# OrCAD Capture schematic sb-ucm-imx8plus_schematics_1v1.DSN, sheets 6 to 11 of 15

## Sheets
6 02. Carrier-board interface: size A3; title: SB-UCM-iMX8PLUS  02. Carrier
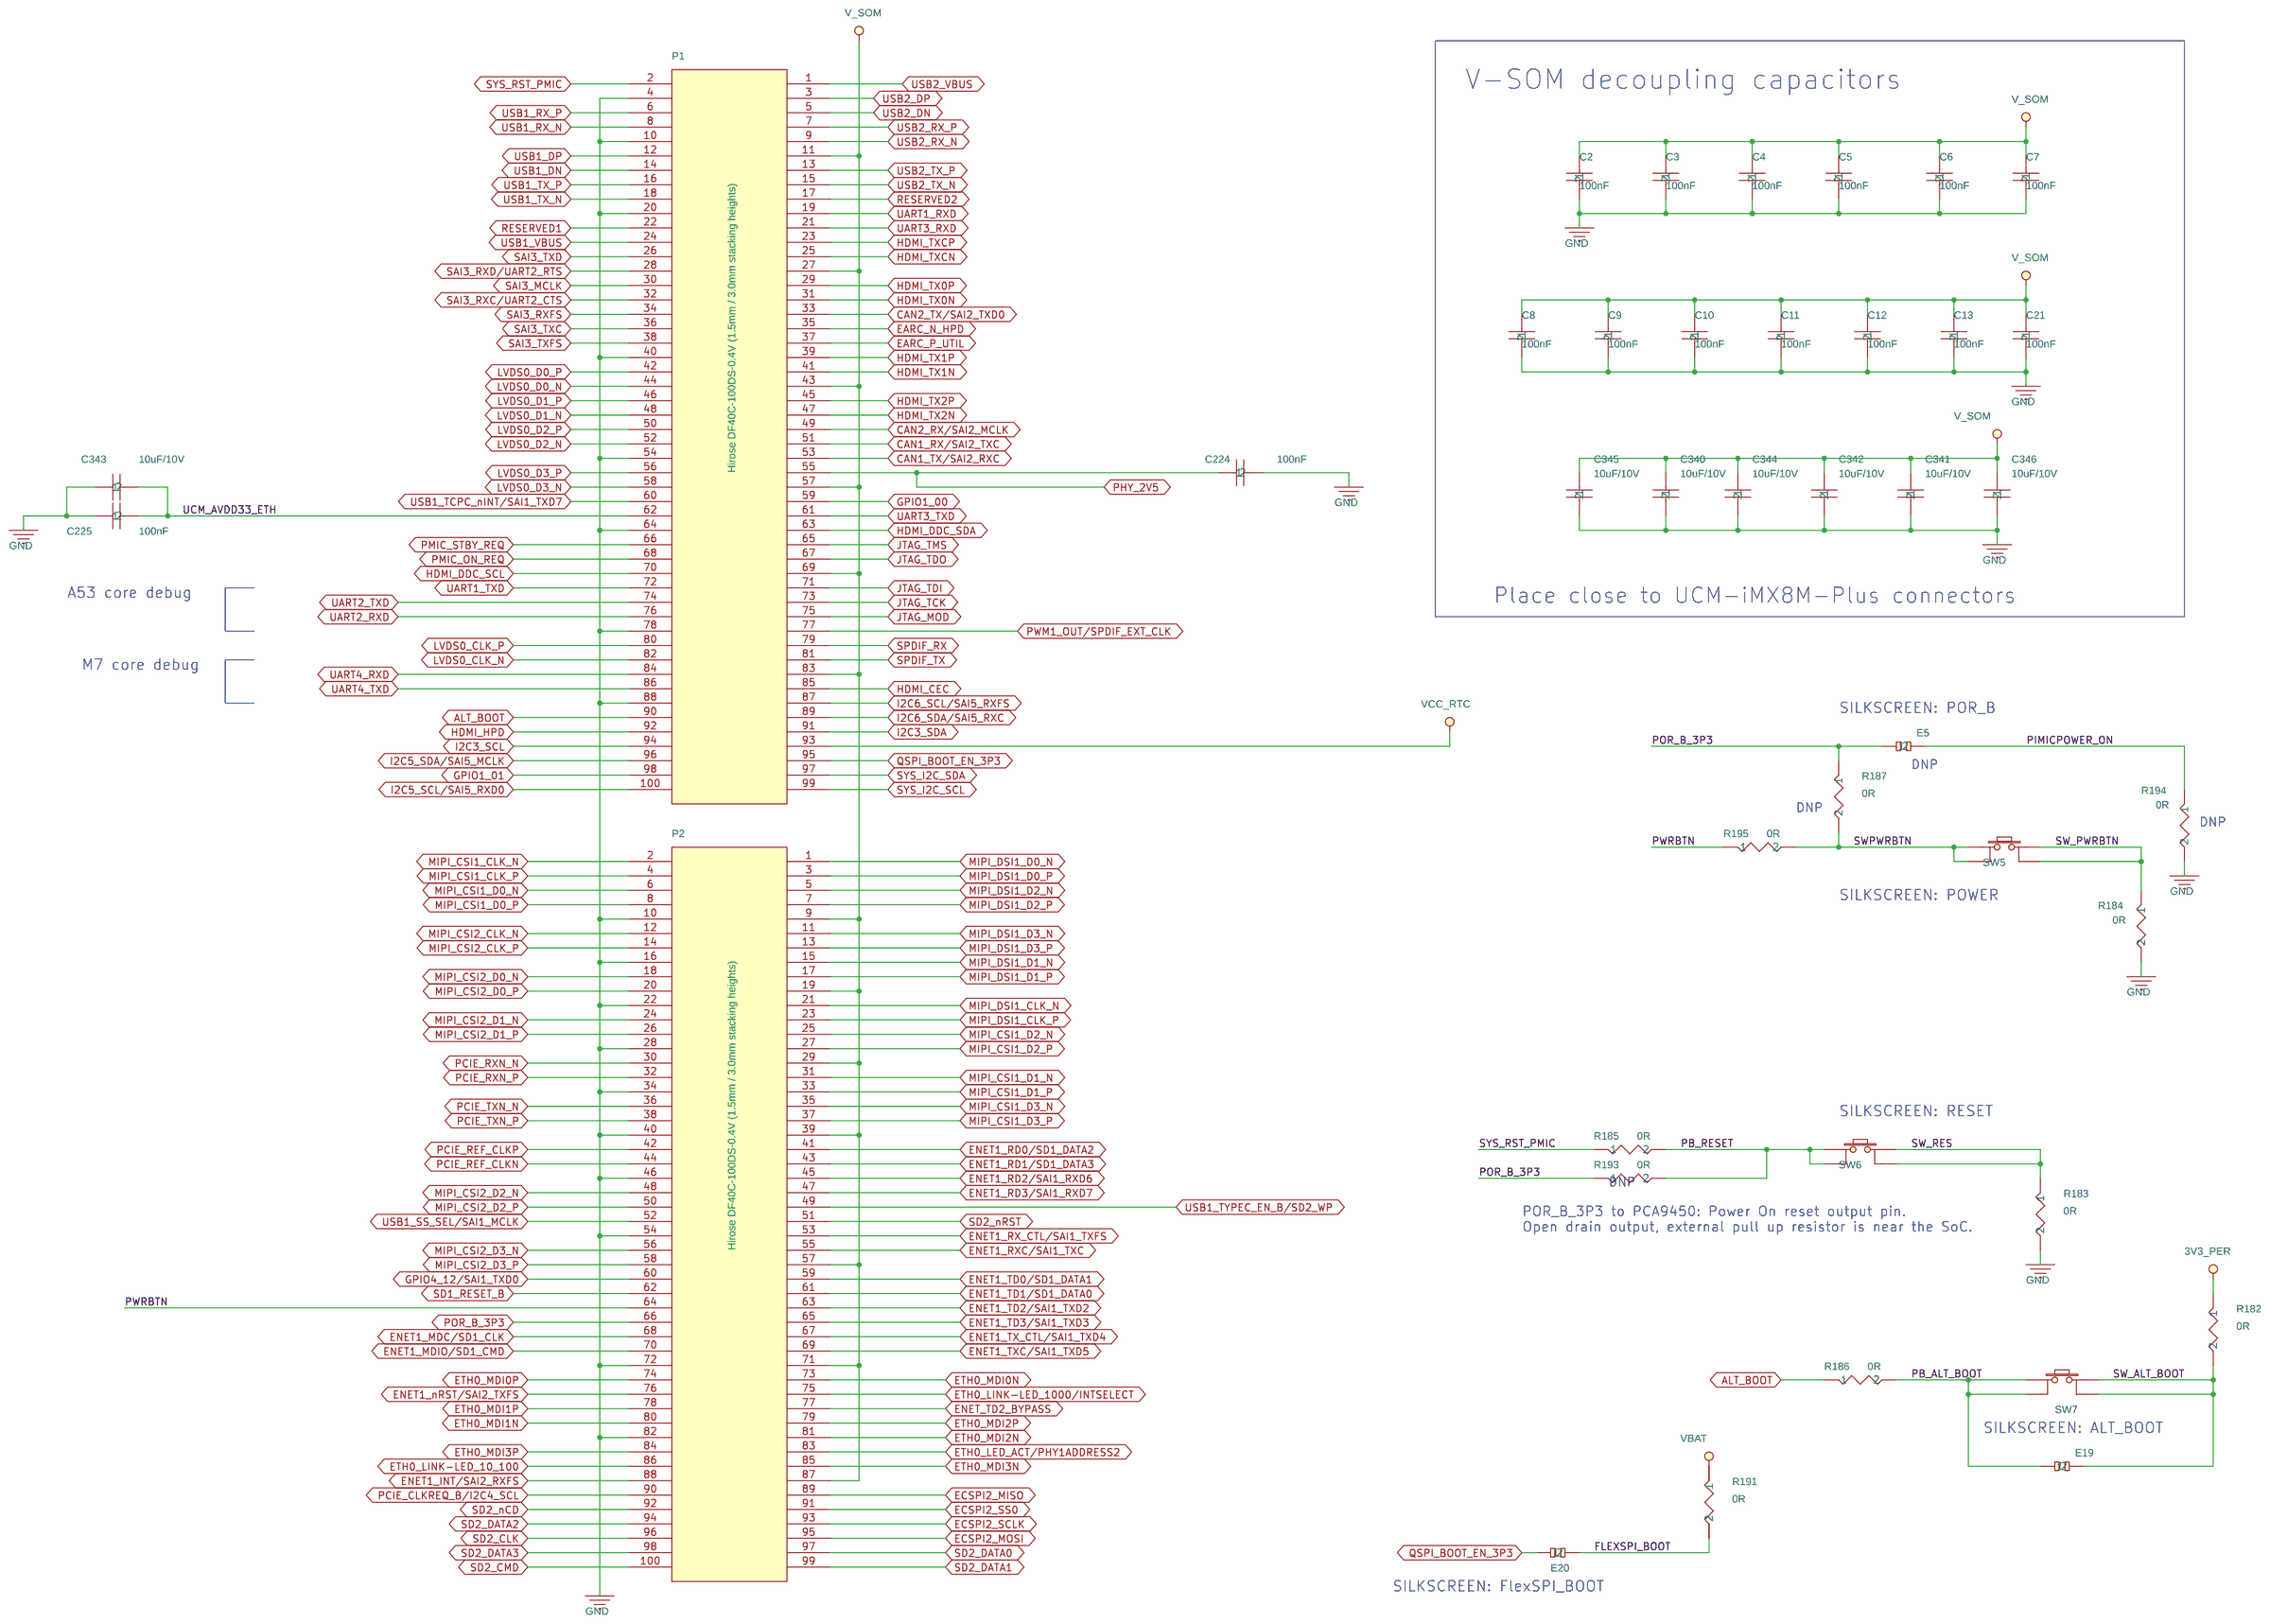
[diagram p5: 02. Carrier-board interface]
7 03. RJ-45 Ethernet connector: size A3; title: SB-UCM-iMX8PLUS      03. Gigabit Ethernet
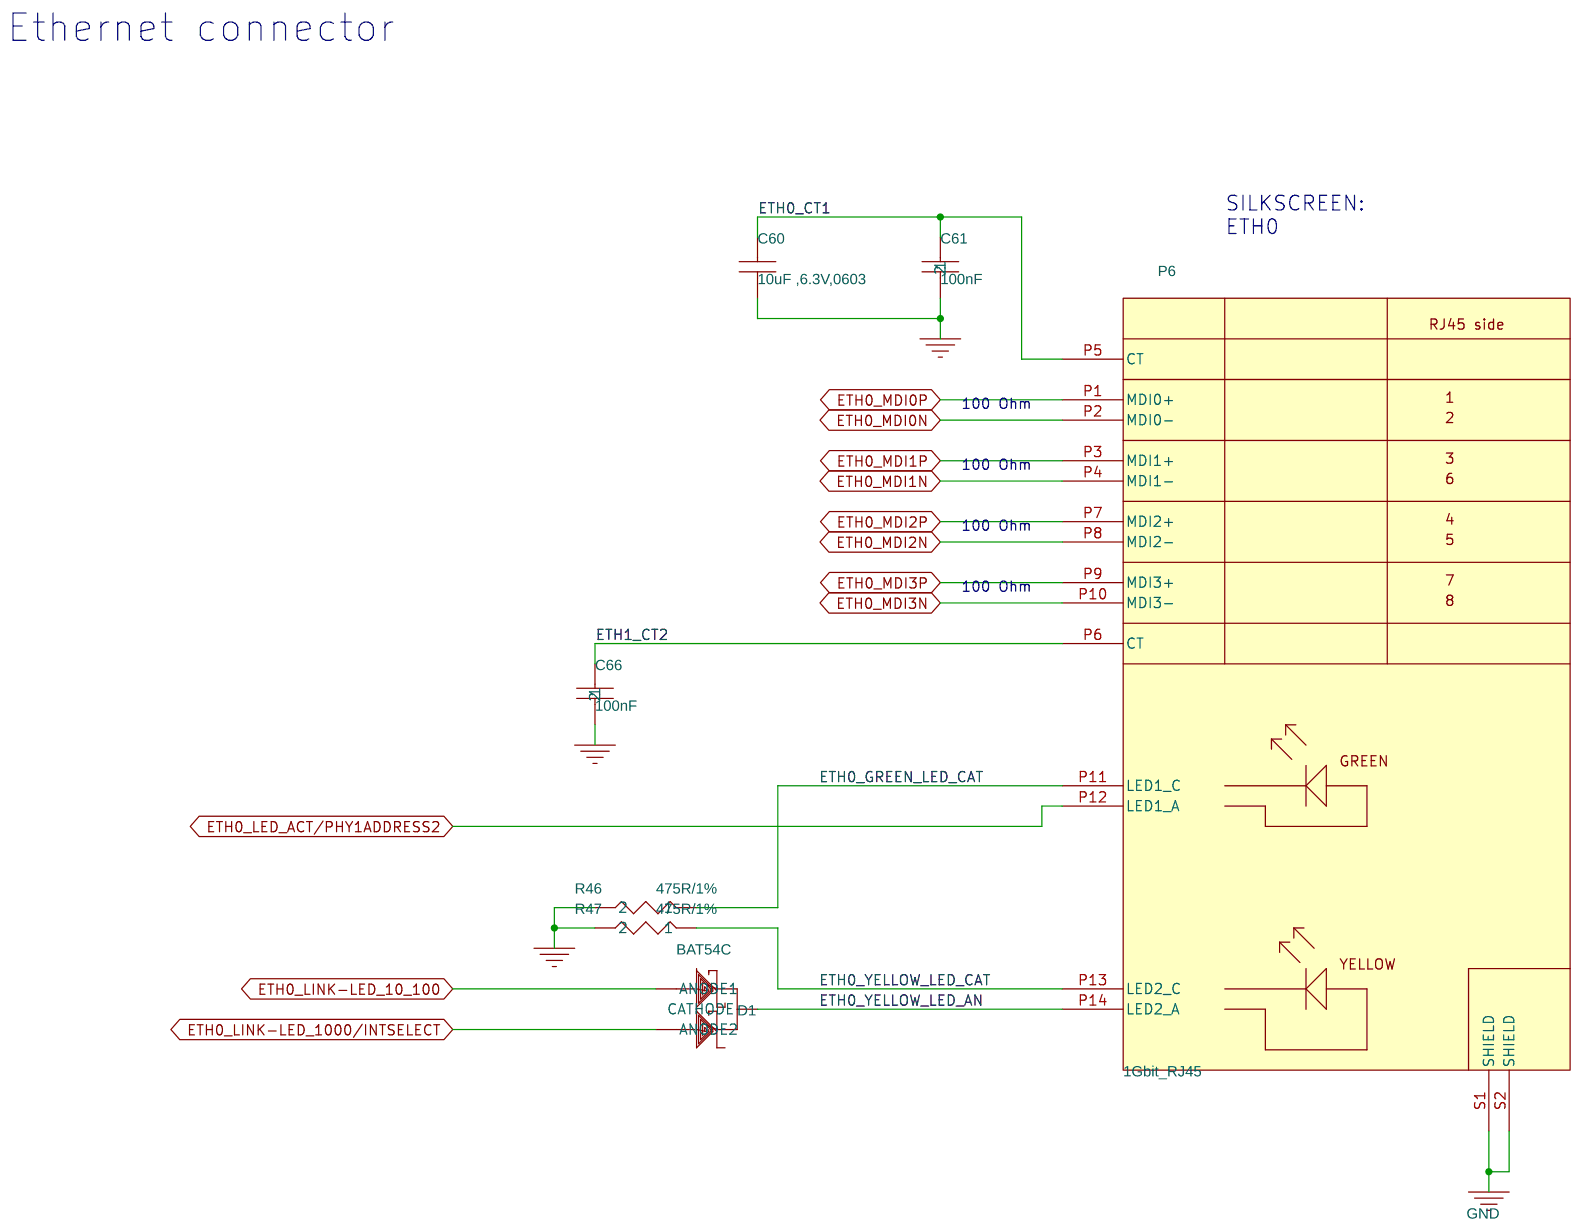
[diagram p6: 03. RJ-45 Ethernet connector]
8 04. USB3.0, Type-C, Host: size A3; title: SB-UCM-iMX8PLUS    04. USB3.0, Type-C, Host
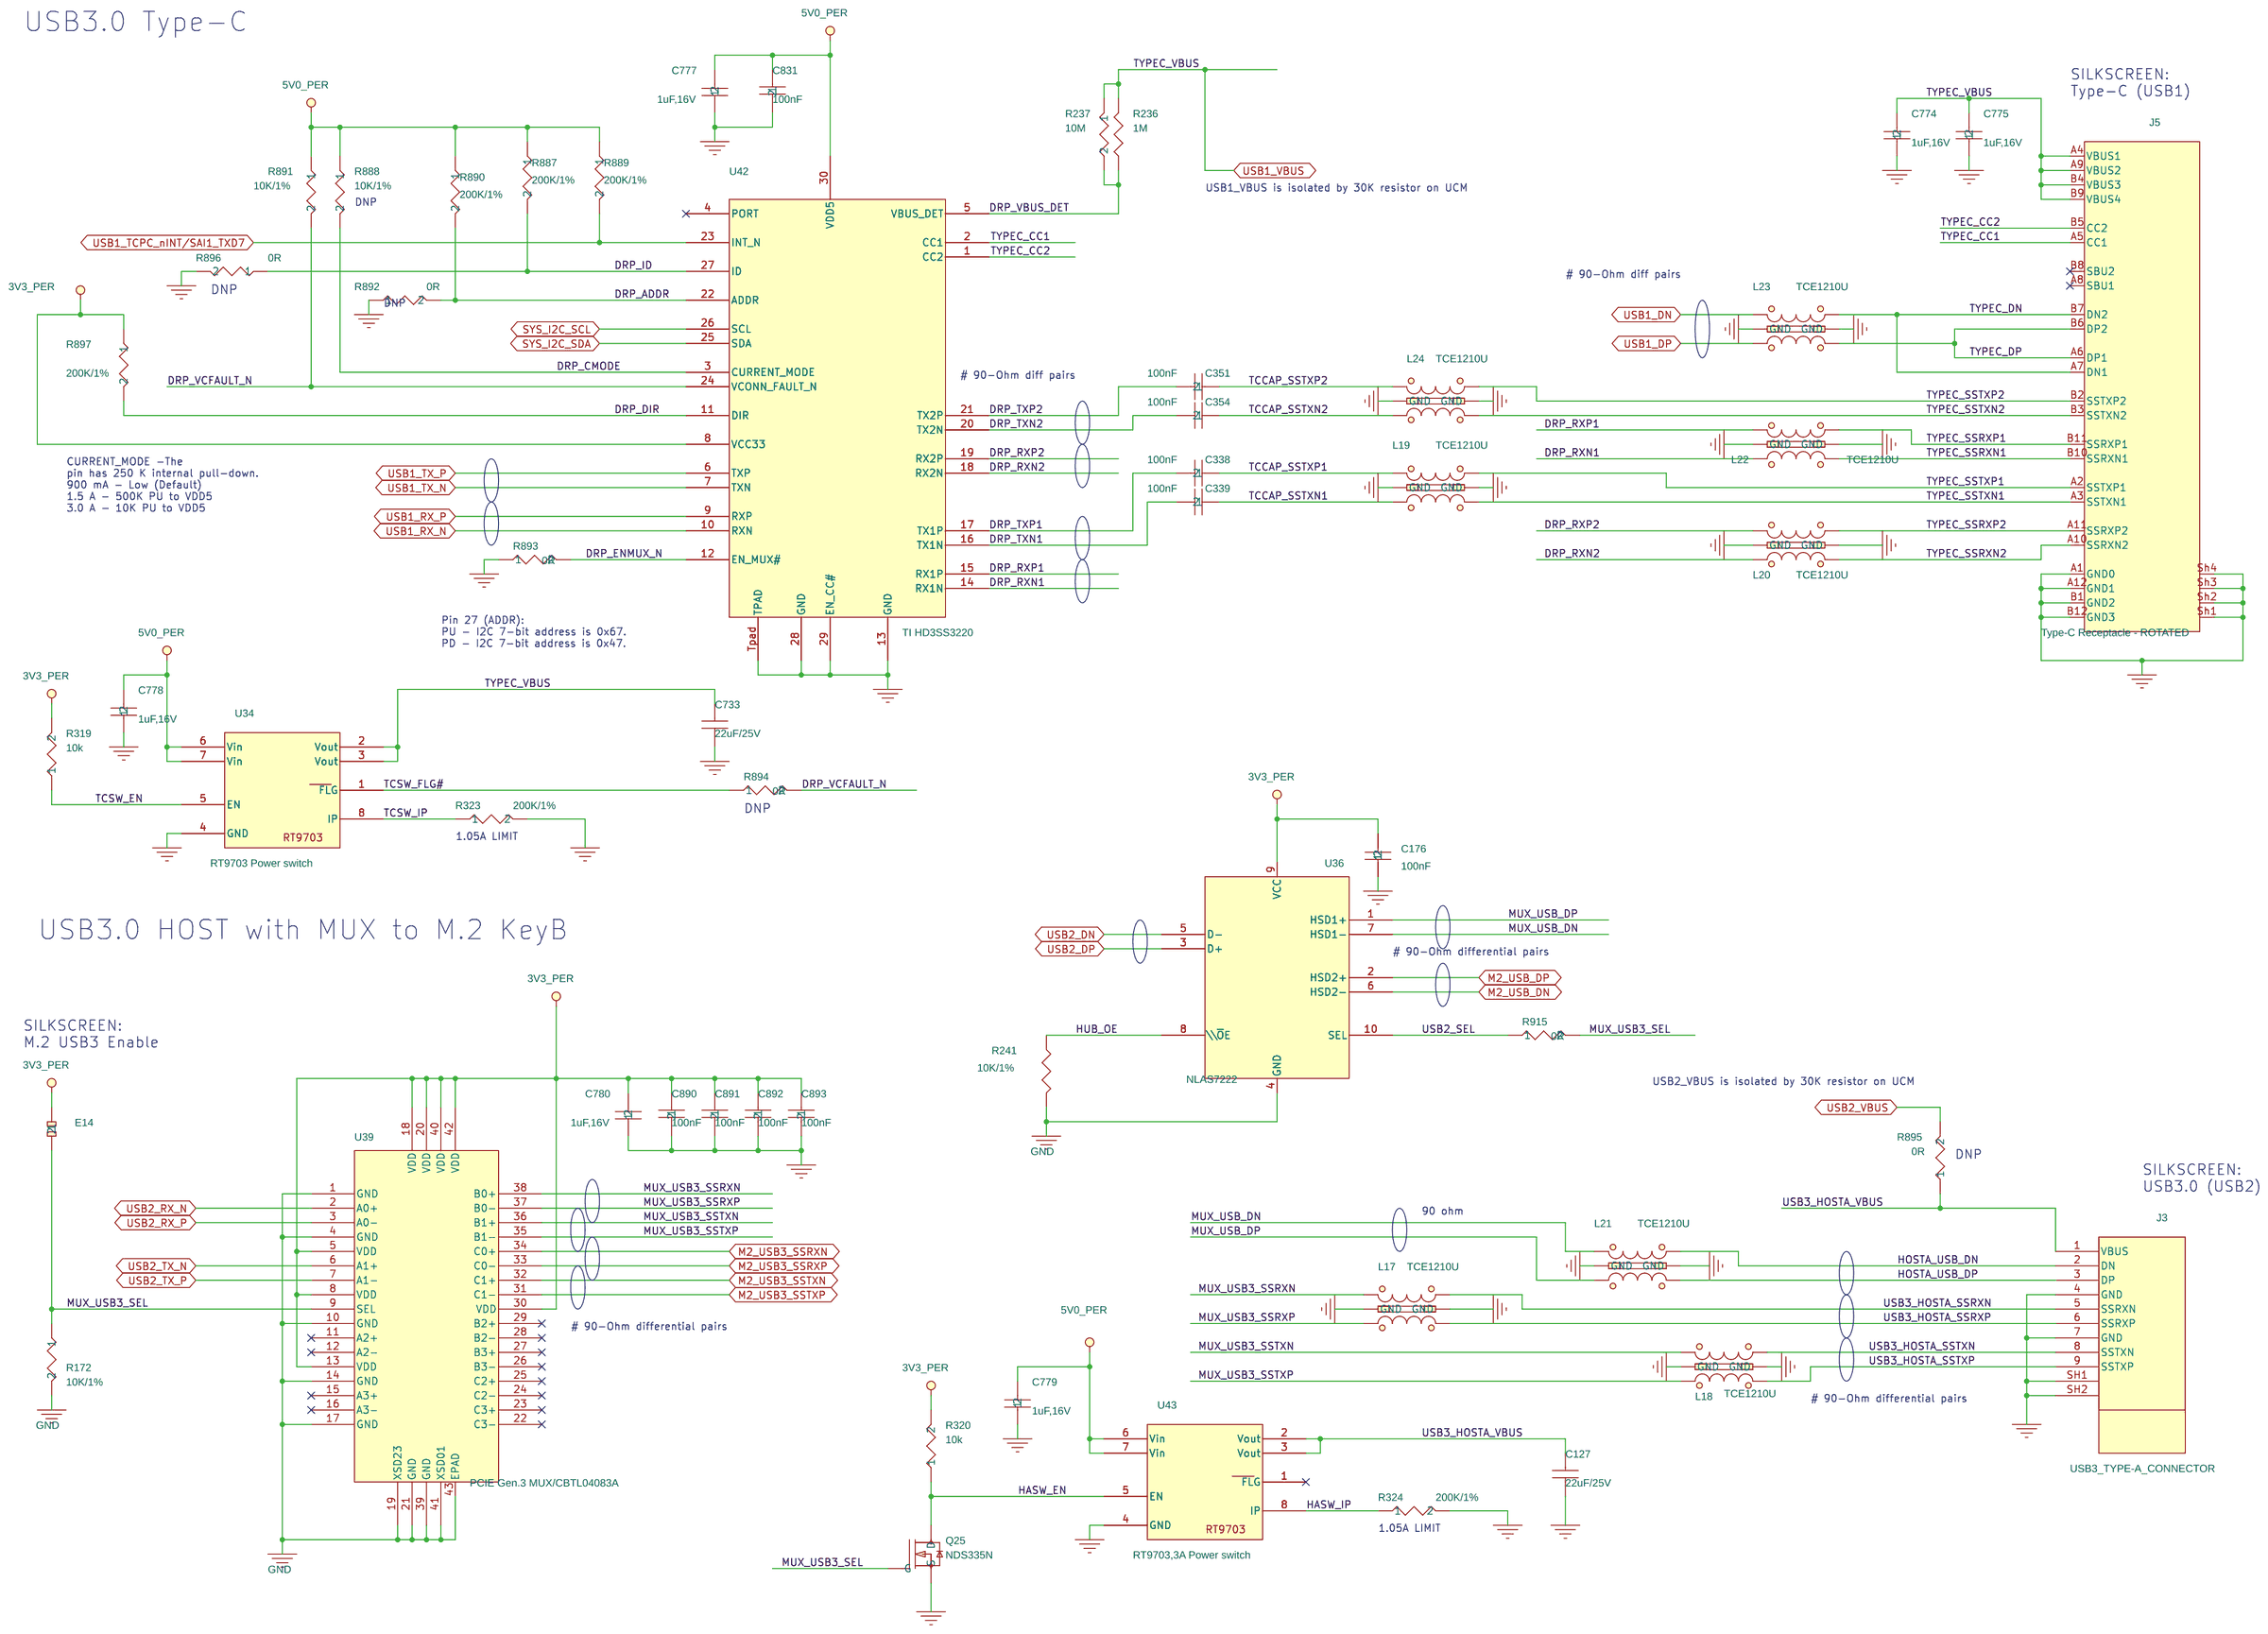
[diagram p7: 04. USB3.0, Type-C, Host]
9 05. Audio Codec: size A3; title: SB-UCM-iMX8PLUS      05. AUDIO,SPDIF
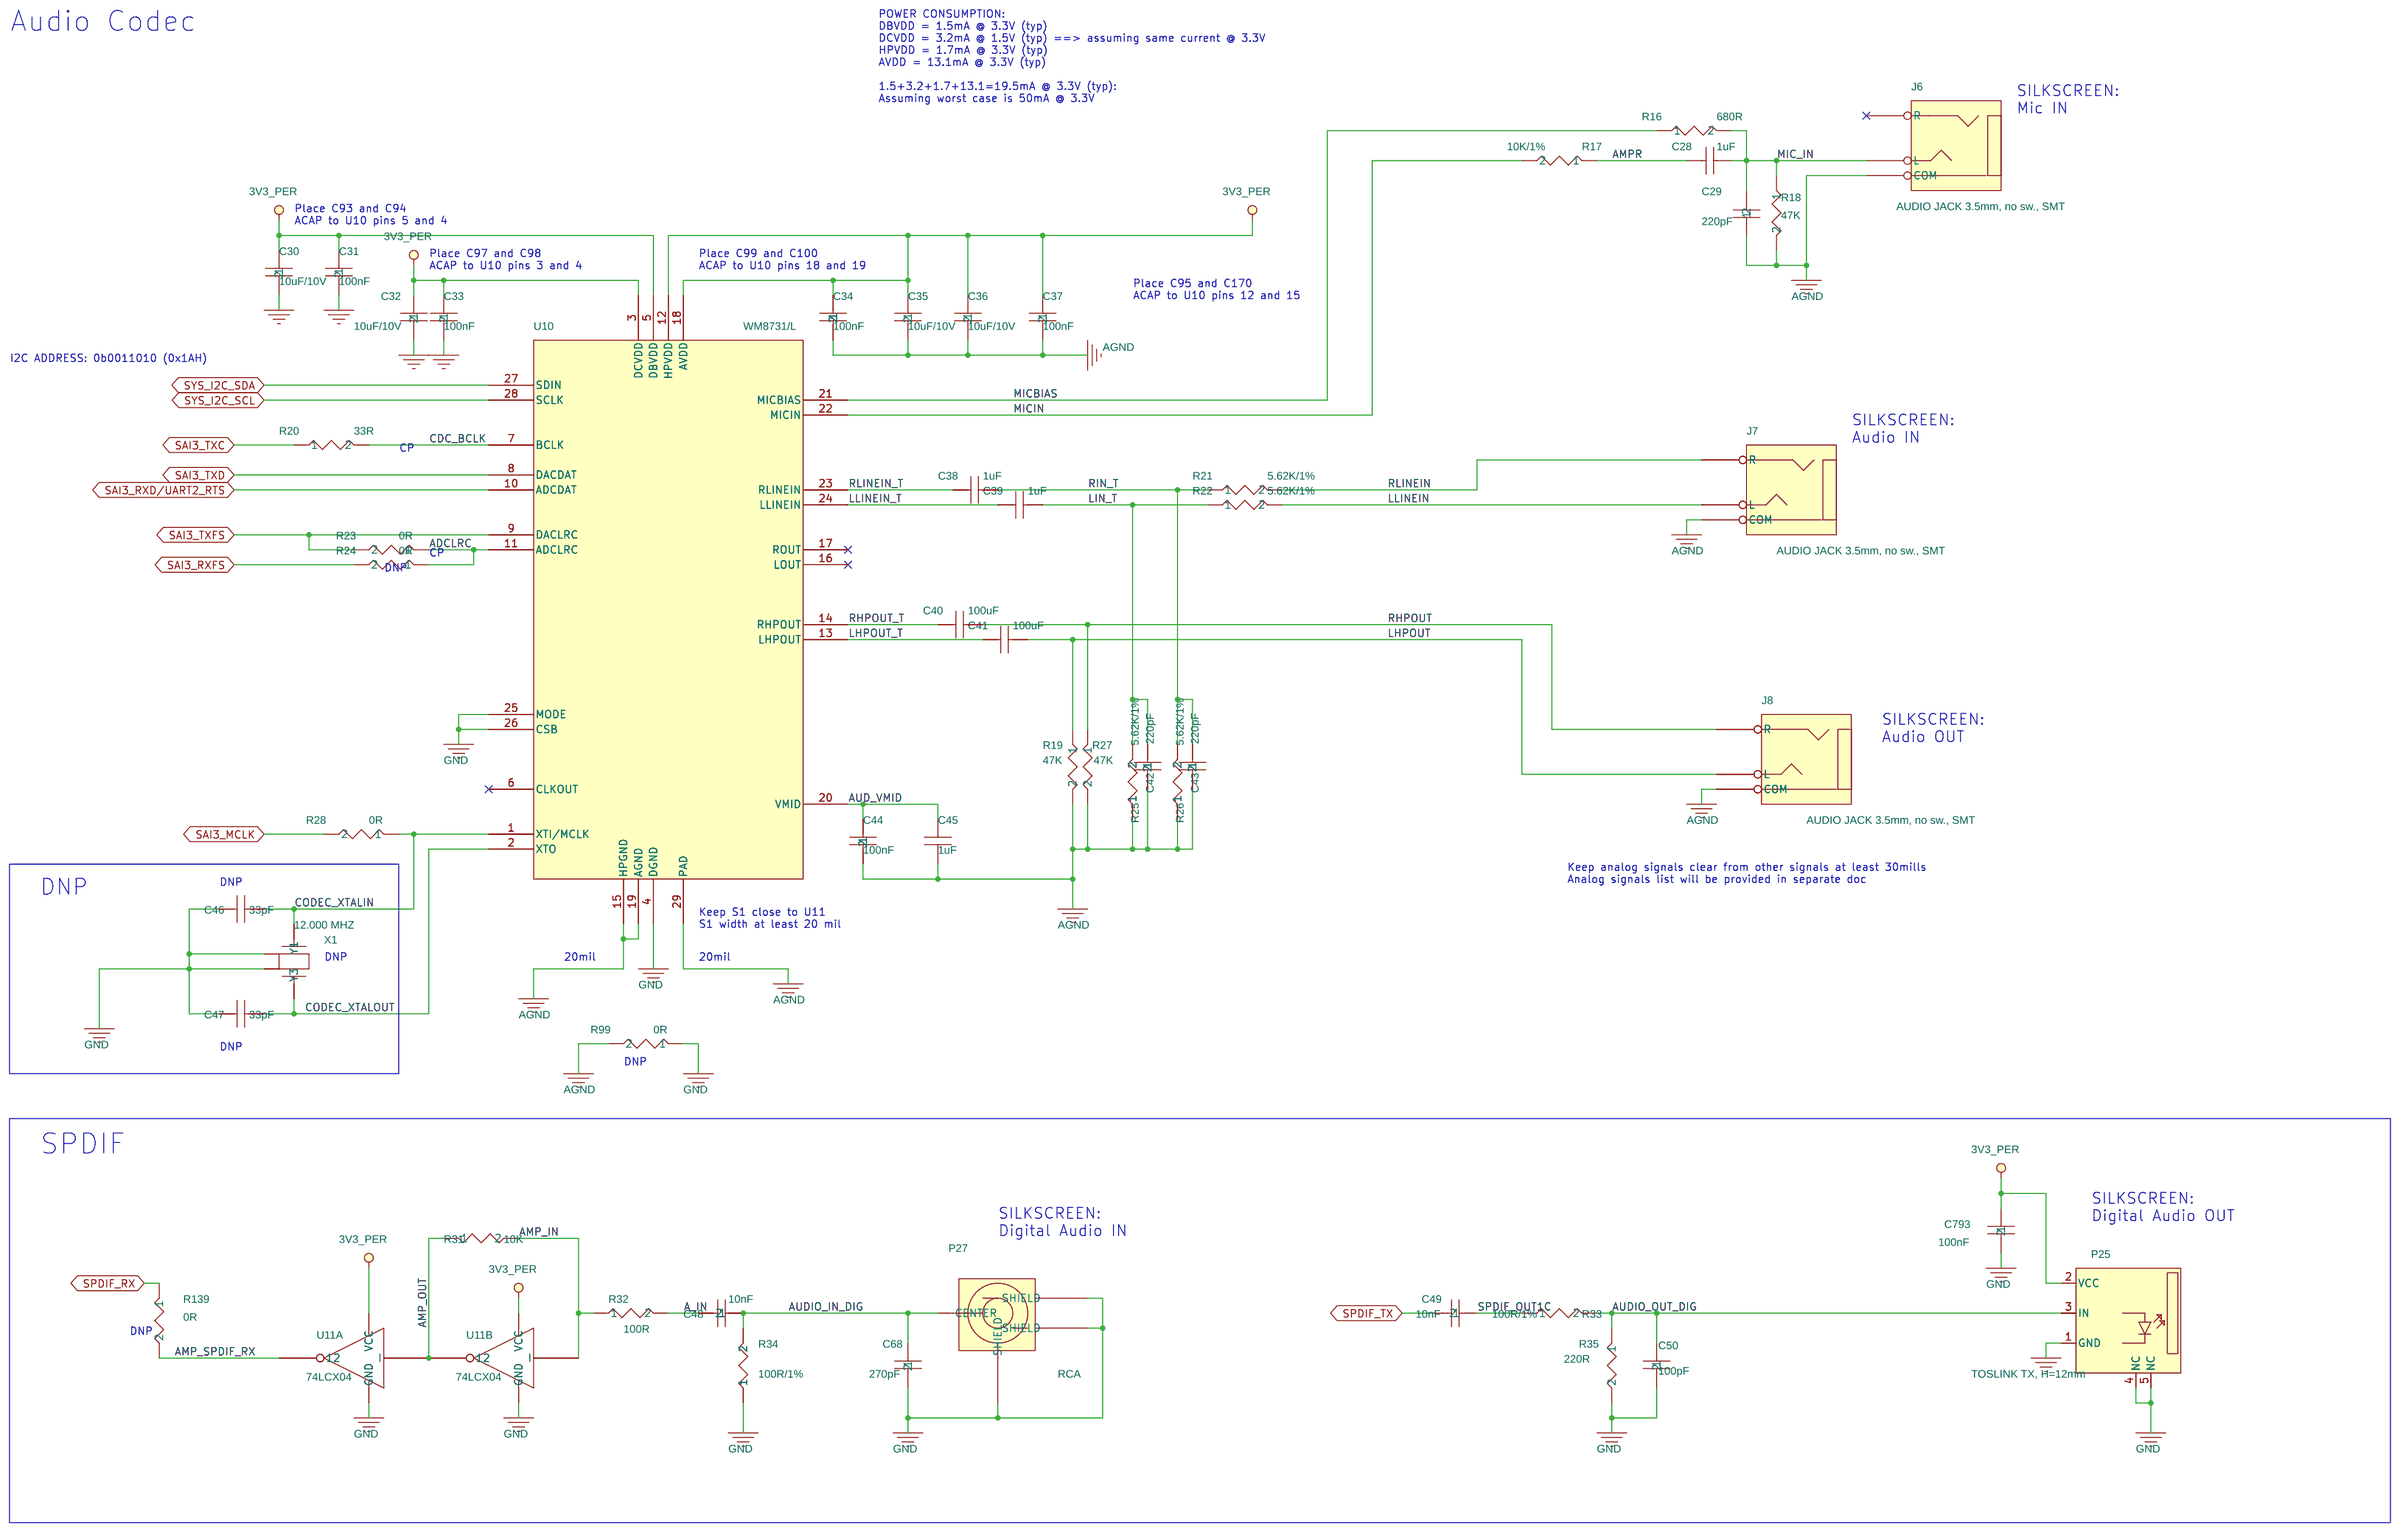
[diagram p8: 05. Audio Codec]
10 06. JTAG, CAN, GPIO Exp., Misc.: size A2; title: SB-UCM-iMX8PLUS    06. JTAG, CAN, GPIO Exp., Misc.
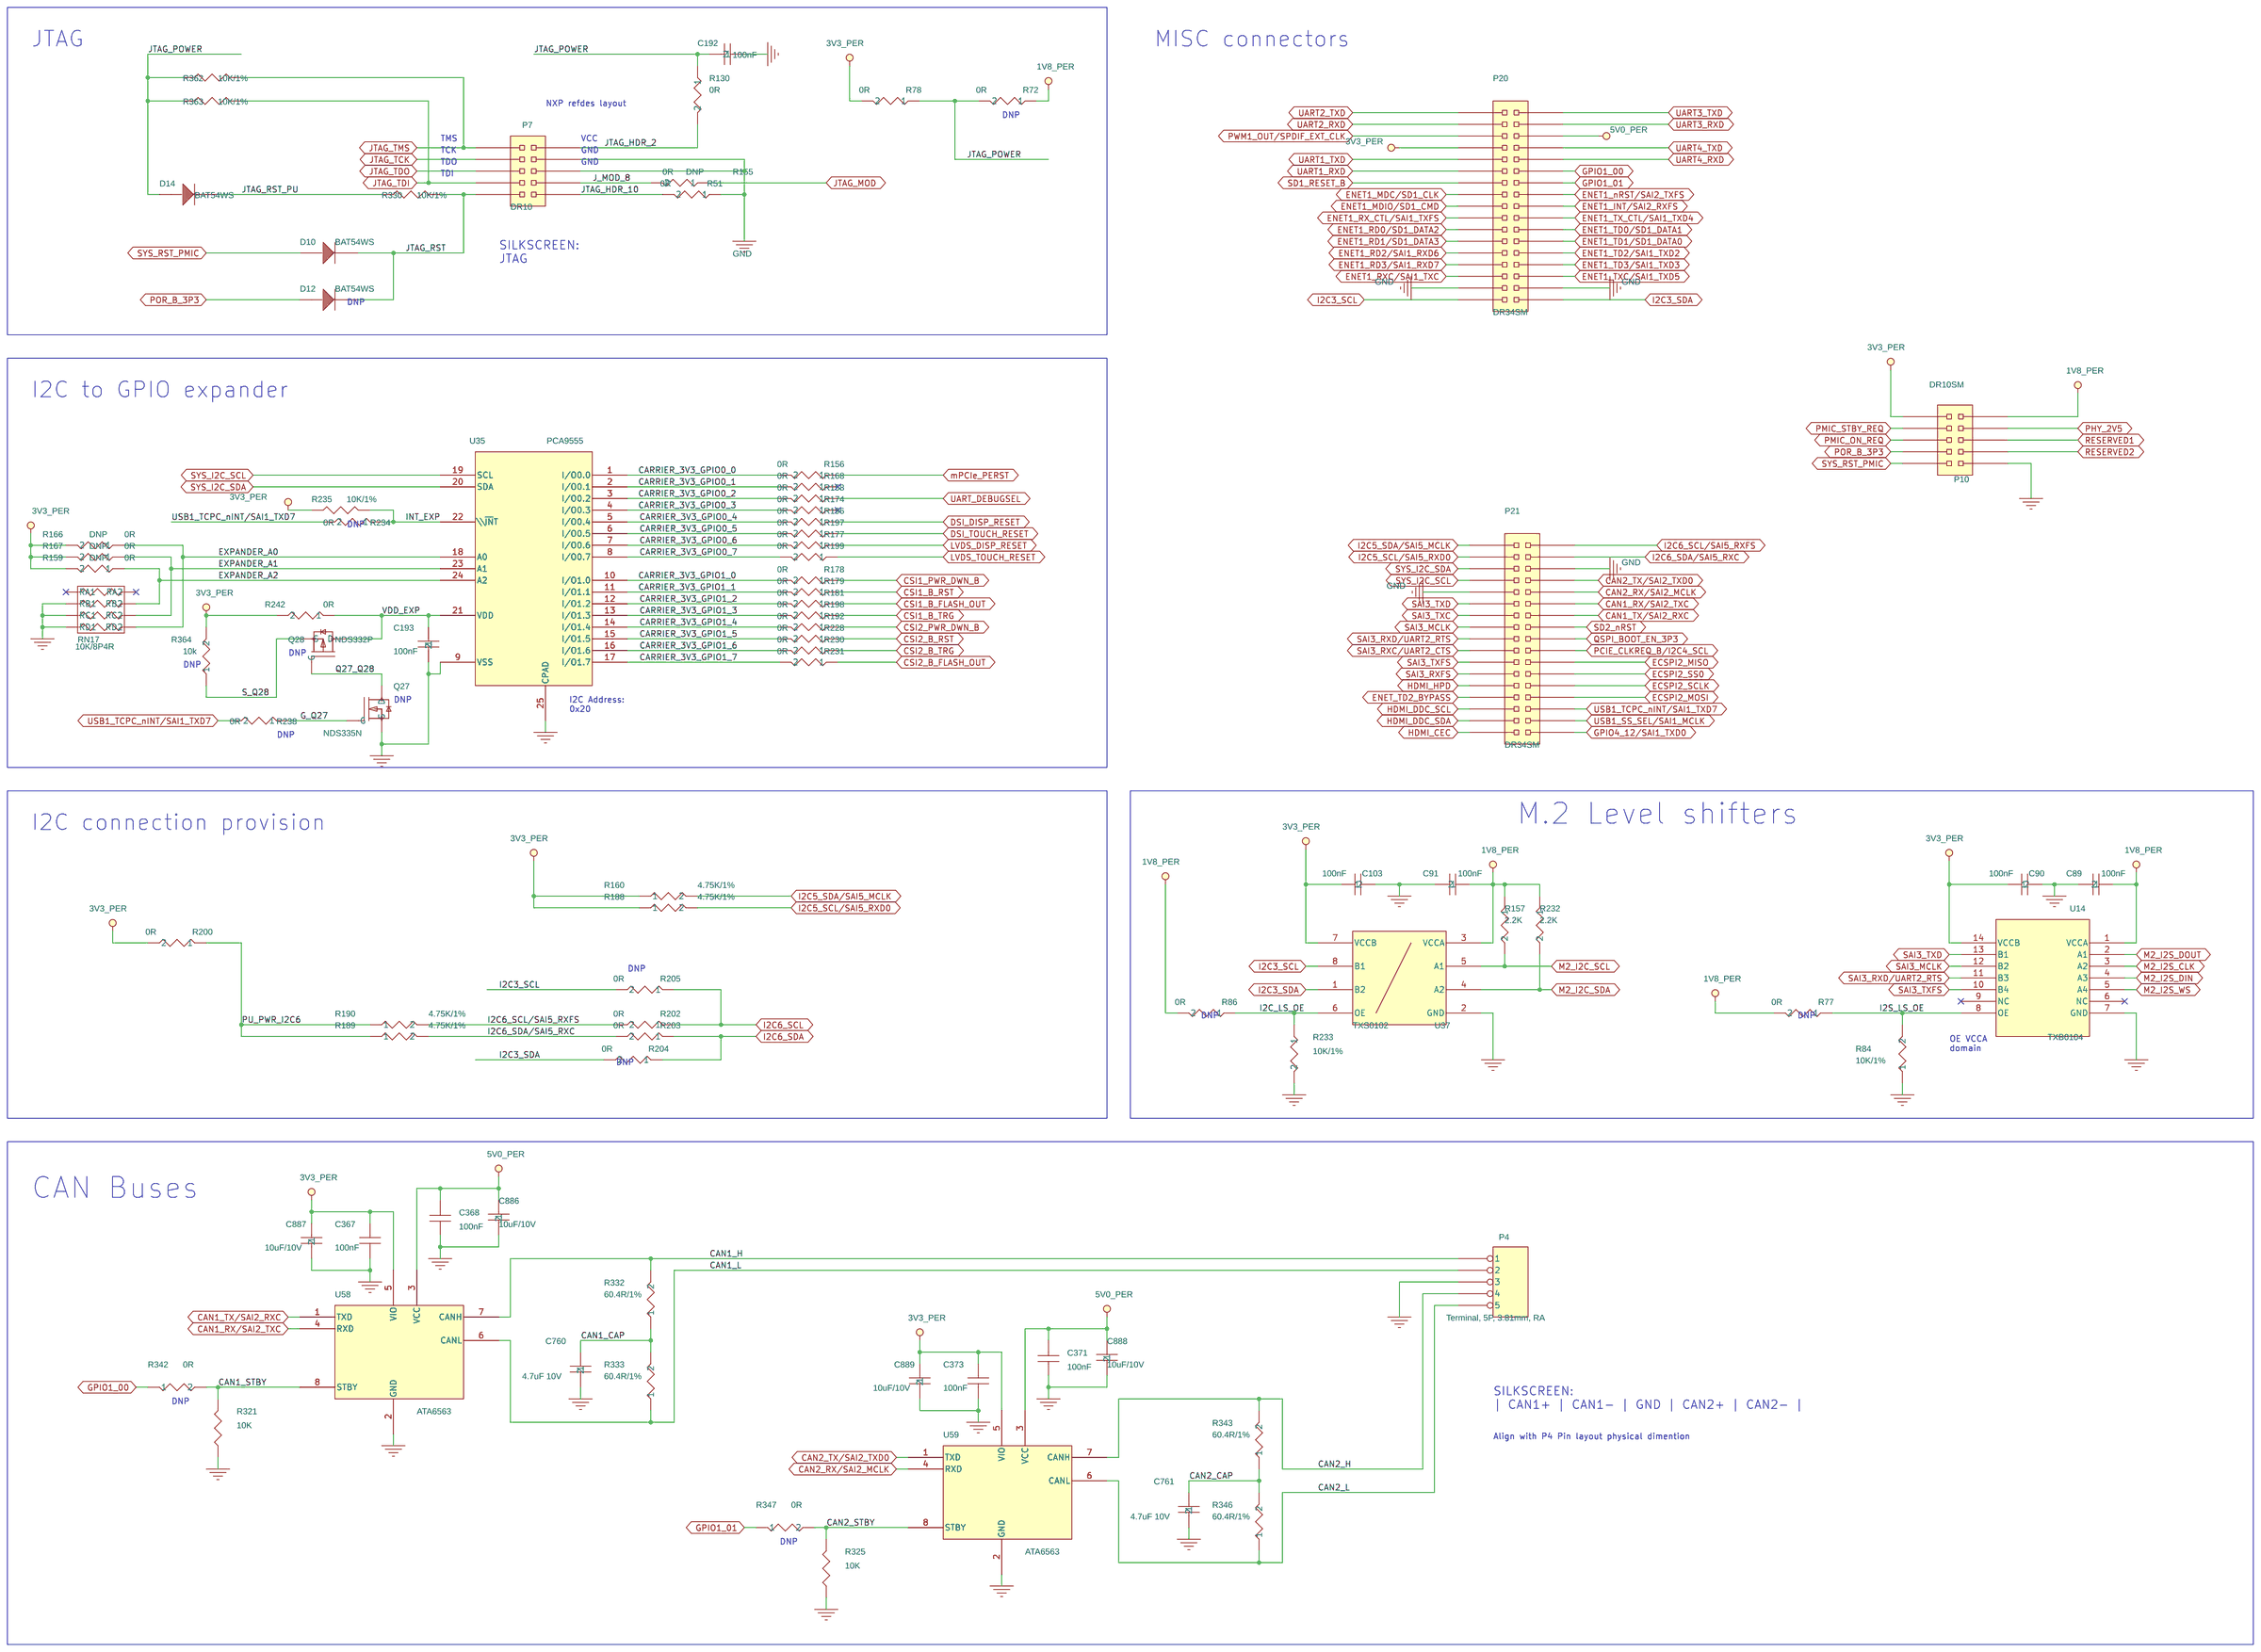
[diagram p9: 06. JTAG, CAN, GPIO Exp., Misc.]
11 07. MIPI-DSI LCD: size A3; title: SB-UCM-iMX8PLUS   07. MIPI-DSI LCD
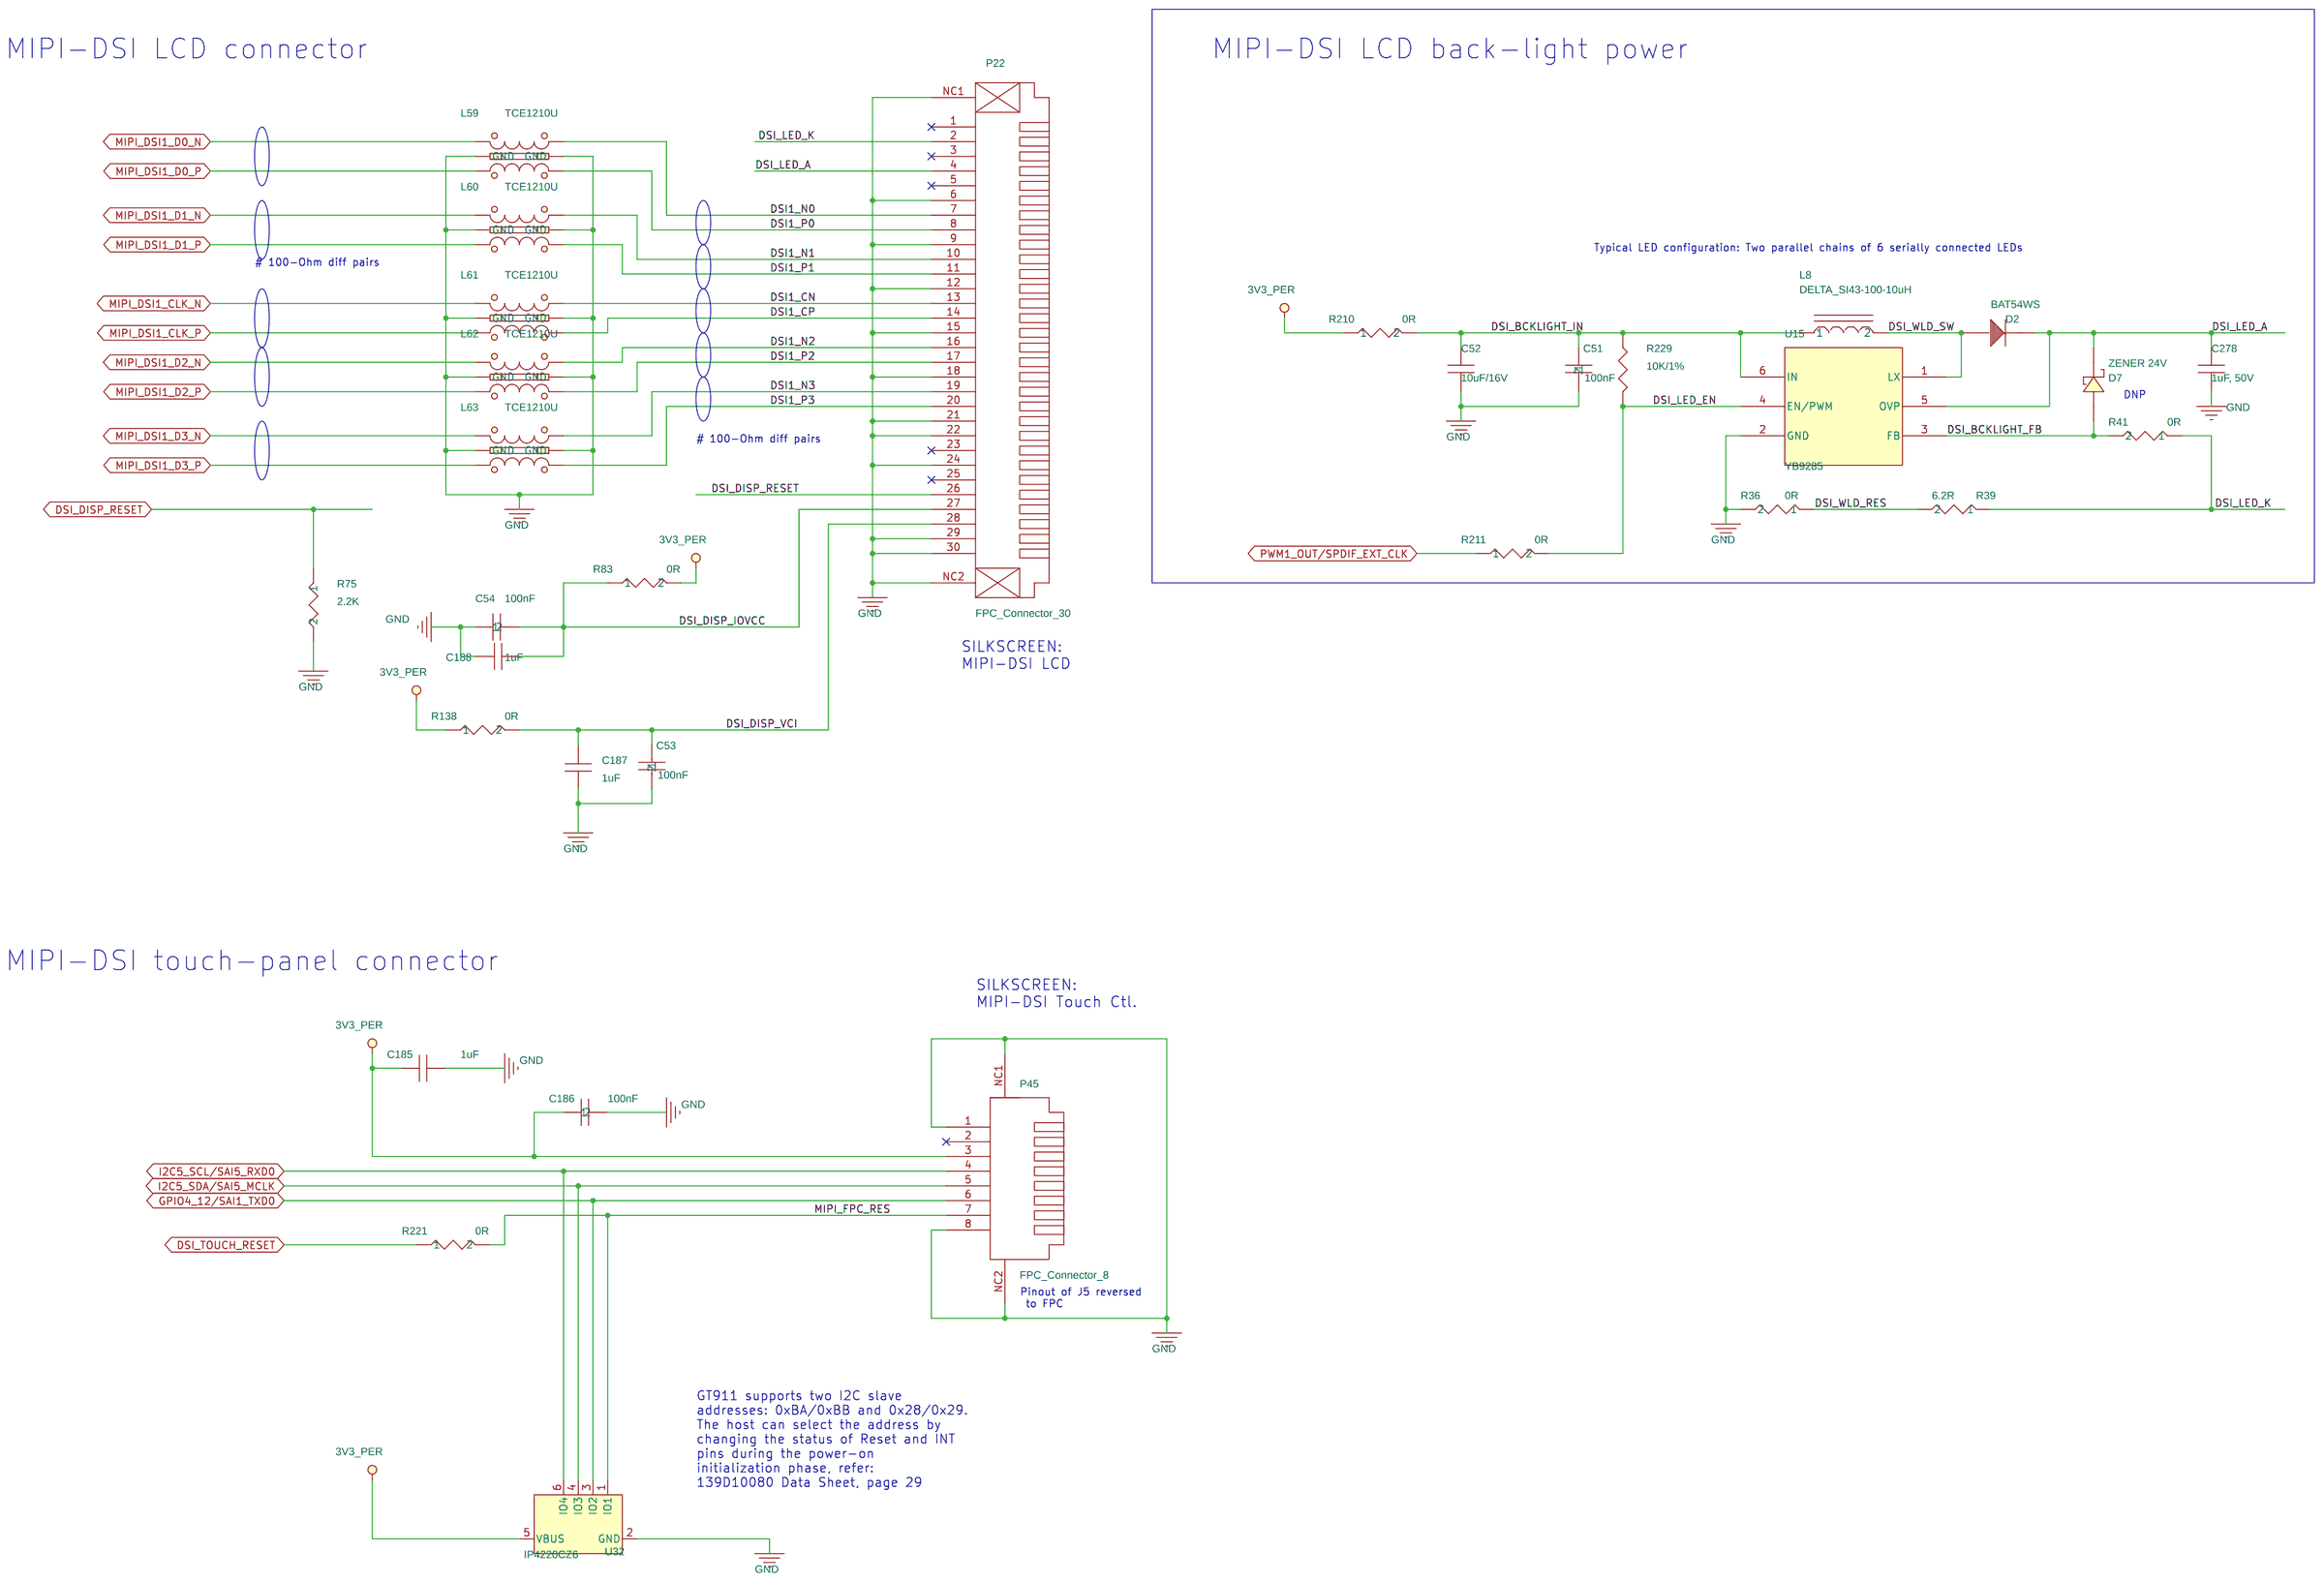
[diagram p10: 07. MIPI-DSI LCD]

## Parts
sheet 02. Carrier-board interface
C2  100nF  [RC0402]
C3  100nF  [RC0402]
C4  100nF  [RC0402]
C5  100nF  [RC0402]
C6  100nF  [RC0402]
C7  100nF  [RC0402]
C8  100nF  [RC0402]
C9  100nF  [RC0402]
C10  100nF  [RC0402]
C11  100nF  [RC0402]
C12  100nF  [RC0402]
C13  100nF  [RC0402]
C21  100nF  [RC0402]
C224  100nF  [RC0402]
C225  100nF  [RC0402]
C340  10uF/10V  [RC0402]
C341  10uF/10V  [RC0402]
C342  10uF/10V  [RC0402]
C343  10uF/10V  [RC0402]
C344  10uF/10V  [RC0402]
C345  10uF/10V  [RC0402]
C346  10uF/10V  [RC0402]
E5  HDR1X2  [1X2THHDR]
E19  HDR1X2  [1X2THHDR]
E20  HDR1X2  [1X2THHDR]
P1  Hirose DF40C-100DS-0.4V (1.5mm / 3.0mm stacking heights)  [B2B04M2X50R]
P2  Hirose DF40C-100DS-0.4V (1.5mm / 3.0mm stacking heights)  [B2B04M2X50R]
R182  0R  [RC0402]
R183  0R  [RC0402]
R184  0R  [RC0402]
R185  0R  [RC0402]
R186  0R  [RC0402]
R187  0R  [RC0402]
R191  0R  [RC0402]
R193  0R  [RC0402]
R194  0R  [RC0402]
R195  0R  [RC0402]
SW5  PushB  [TACTSW6x6SM]
SW6  PushB  [TACTSW6x6SM]
SW7  PushB  [TACTSW6x6SM]
sheet 03. RJ-45 Ethernet connector
C60  10uF ,6.3V,0603  [RC0603]
C61  100nF  [RC0402]
C66  100nF  [RC0402]
D1  BAT54C  [SOT23]
P6  1Gbit_RJ45  [DUSBRJ-1G]
R46  475R/1%  [RC0402]
R47  475R/1%  [RC0402]
sheet 04. USB3.0, Type-C, Host
C127  22uF/25V  [C0805]
C176  100nF  [RC0402]
C338  100nF  [RC0402]
C339  100nF  [RC0402]
C351  100nF  [RC0402]
C354  100nF  [RC0402]
C733  22uF/25V  [C0805]
C774  1uF,16V  [RC0402]
C775  1uF,16V  [RC0402]
C777  1uF,16V  [RC0402]
C778  1uF,16V  [RC0402]
C779  1uF,16V  [RC0402]
C780  1uF,16V  [RC0402]
C831  100nF  [RC0402]
C890  100nF  [RC0402]
C891  100nF  [RC0402]
C892  100nF  [RC0402]
C893  100nF  [RC0402]
E14  HDR1X2  [1X2THHDR]
J3  USB3_TYPE-A_CONNECTOR  [USB3_TYPEA]
J5  Type-C Receptacle - ROTATED  [USB3_1-C-SM]
L17  TCE1210U  [EMI1012-ESD]
L18  TCE1210U  [EMI1012-ESD]
L19  TCE1210U  [EMI1012-ESD]
L20  TCE1210U  [EMI1012-ESD]
L21  TCE1210U  [EMI1012-ESD]
L22  TCE1210U  [EMI1012-ESD]
L23  TCE1210U  [EMI1012-ESD]
L24  TCE1210U  [EMI1012-ESD]
Q25  NDS335N  [SOT23]
R172  10K/1%  [RC0402]
R236  1M  [RC0402]
R237  10M  [RC0402]
R241  10K/1%  [RC0402]
R319  10k  [RC0402]
R320  10k  [RC0402]
R323  200K/1%  [RC0402]
R324  200K/1%  [RC0402]
R887  200K/1%  [RC0402]
R888  10K/1%  [RC0402]
R889  200K/1%  [RC0402]
R890  200K/1%  [RC0402]
R891  10K/1%  [RC0402]
R892  0R  [RC0402]
R893  0R  [RC0402]
R894  0R  [RC0402]
R895  0R  [RC0402]
R896  0R  [RC0402]
R897  200K/1%  [RC0402]
R915  0R  [RC0402]
U34  RT9703 Power switch  [SO8-150]
U36  NLAS7222  [MO-255U1418E]
U39  PCIE Gen.3 MUX/CBTL04083A  [MO-220VMFD-2x7.5]
U42  TI HD3SS3220  [QFN2_6x4_6-30]
U43  RT9703,3A Power switch  [SO8-150]
sheet 05. Audio Codec
C28  1uF  [RC0402]
C29  220pF  [RC0603]
C30  10uF/10V  [RC0402]
C31  100nF  [RC0402]
C32  10uF/10V  [RC0402]
C33  100nF  [RC0402]
C34  100nF  [RC0402]
C35  10uF/10V  [RC0402]
C36  10uF/10V  [RC0402]
C37  100nF  [RC0402]
C38  1uF  [RC0402]
C39  1uF  [RC0402]
C40  100uF  [C1206]
C41  100uF  [C1206]
C42  220pF  [RC0603]
C43  220pF  [RC0603]
C44  100nF  [RC0402]
C45  1uF  [RC0402]
C46  33pF  [RC0402]
C47  33pF  [RC0402]
C48  10nF  [RC0402]
C49  10nF  [RC0402]
C50  100pF  [RC0402]
C68  270pF  [RC0402]
C793  100nF  [RC0402]
J6  AUDIO JACK 3.5mm, no sw., SMT  [AJ35-3P-SM]
J7  AUDIO JACK 3.5mm, no sw., SMT  [AJ35-3P-SM]
J8  AUDIO JACK 3.5mm, no sw., SMT  [AJ35-3P-SM]
P25  TOSLINK TX, H=12mm  [FO10X12-12]
P27  RCA
R16  680R  [RC0402]
R17  10K/1%  [RC0402]
R18  47K  [RC0402]
R19  47K  [RC0402]
R20  33R  [RC0402]
R21  5.62K/1%  [RC0402]
R22  5.62K/1%  [RC0402]
R23  0R  [RC0402]
R24  0R  [RC0402]
R25  5.62K/1%  [RC0402]
R26  5.62K/1%  [RC0402]
R27  47K  [RC0402]
R28  0R  [RC0402]
R31  10K  [RC0402]
R32  100R  [RC0402]
R33  100R/1%  [RC0402]
R34  100R/1%  [RC0402]
R35  220R  [RC0402]
R99  0R  [RC0402]
R139  0R  [RC0402]
U10  WM8731/L  [MO-220VHHD-1]
U11  74LCX04  [TSSOP-14]  (sections A,B,F)
X1  12.000 MHZ  [OSC3225]
sheet 06. JTAG, CAN, GPIO Exp., Misc.
C89  100nF  [RC0402]
C90  100nF  [RC0402]
C91  100nF  [RC0402]
C103  100nF  [RC0402]
C192  100nF  [RC0402]
C193  100nF  [RC0402]
C367  100nF  [RC0402]
C368  100nF  [RC0402]
C371  100nF  [RC0402]
C373  100nF  [RC0402]
C760  4.7uF 10V  [RC0402]
C761  4.7uF 10V  [RC0402]
C886  10uF/10V  [RC0402]
C887  10uF/10V  [RC0402]
C888  10uF/10V  [RC0402]
C889  10uF/10V  [RC0402]
D10  BAT54WS  [SOD-323]
D12  BAT54WS  [SOD-323]
D14  BAT54WS  [SOD-323]
P4  Terminal, 5P, 3.81mm, RA  [TB3.81mmRA-5P]
P7  DR10  [2X5THHDR]
P10  DR10SM  [2X5SMHDR]
P20  DR34SM  [2X17SMHDR]
P21  DR34SM  [2X17SMHDR]
Q27  NDS335N  [SOT23]
Q28  NDS332P  [SOT23]
R51  0R  [RC0402]
R72  0R  [RC0402]
R77  0R  [RC0402]
R78  0R  [RC0402]
R84  10K/1%  [RC0402]
R86  0R  [RC0402]
R130  0R  [RC0402]
R155  0R  [RC0402]
R156  0R  [RC0402]
R157  2.2K  [RC0402]
R158  0R  [RC0402]
R159  0R  [RC0402]
R160  4.75K/1%  [RC0402]
R166  0R  [RC0402]
R167  0R  [RC0402]
R168  0R  [RC0402]
R174  0R  [RC0402]
R177  0R  [RC0402]
R178  0R  [RC0402]
R179  0R  [RC0402]
R181  0R  [RC0402]
R188  4.75K/1%  [RC0402]
R189  4.75K/1%  [RC0402]
R190  4.75K/1%  [RC0402]
R192  0R  [RC0402]
R196  0R  [RC0402]
R197  0R  [RC0402]
R198  0R  [RC0402]
R199  0R  [RC0402]
R200  0R  [RC0402]
R202  0R  [RC0402]
R203  0R  [RC0402]
R204  0R  [RC0402]
R205  0R  [RC0402]
R228  0R  [RC0402]
R230  0R  [RC0402]
R231  0R  [RC0402]
R232  2.2K  [RC0402]
R233  10K/1%  [RC0402]
R234  0R  [RC0402]
R235  10K/1%  [RC0402]
R238  0R  [RC0402]
R242  0R  [RC0402]
R321  10K  [RC0402]
R325  10K  [RC0402]
R330  10K/1%  [RC0402]
R332  60.4R/1%  [RC0402]
R333  60.4R/1%  [RC0402]
R342  0R  [RC0402]
R343  60.4R/1%  [RC0402]
R346  60.4R/1%  [RC0402]
R347  0R  [RC0402]
R362  10K/1%  [RC0402]
R363  10K/1%  [RC0402]
R364  10k  [RC0402]
RN17  10K/8P4R  [RESNET8P0805]
U14  TXB0104  [TSSOP-14]
U35  PCA9555  [QFN4x4-24]
U37  TXS0102  [MO-187DA-8]
U58  ATA6563  [SOI8-150]
U59  ATA6563  [SOI8-150]
sheet 07. MIPI-DSI LCD
C51  100nF  [RC0402]
C52  10uF/16V  [RC0603]
C53  100nF  [RC0402]
C54  100nF  [RC0402]
C185  1uF  [RC0402]
C186  100nF  [RC0402]
C187  1uF  [RC0402]
C188  1uF  [RC0402]
C278  1uF, 50V  [RC0603]
D2  BAT54WS  [SOD-323]
D7  ZENER 24V  [SOD-123]
L8  DELTA_SI43-100-10uH  [IND4x4x2_5]
L59  TCE1210U  [EMI1012-ESD]
L60  TCE1210U  [EMI1012-ESD]
L61  TCE1210U  [EMI1012-ESD]
L62  TCE1210U  [EMI1012-ESD]
L63  TCE1210U  [EMI1012-ESD]
P22  FPC_Connector_30  [FPC_30]
P45  FPC_Connector_8  [FPC_8]
R36  0R  [RC0402]
R39  6.2R  [RC0402]
R41  0R  [RC0402]
R75  2.2K  [RC0402]
R83  0R  [RC0402]
R138  0R  [RC0402]
R210  0R  [RC0402]
R211  0R  [RC0402]
R221  0R  [RC0402]
R229  10K/1%  [RC0402]
U15  YB9285  [SOT23-6L]
U32  IP4220CZ6  [SOT23-6L]

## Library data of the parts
C2 = 100nF,_10V,_X7R,_10%,_0402_6: CLABCONF0: =SB-UCMIMX8PLUS; P/N: 151B10400S
C3 = 100nF,_10V,_X7R,_10%,_0402_9: CLABCONF0: =SB-UCMIMX8PLUS; P/N: 151B10400S
C4 = 100nF,_10V,_X7R,_10%,_0402_1: CLABCONF0: =SB-UCMIMX8PLUS; P/N: 151B10400S
C5 = 100nF,_10V,_X7R,_10%,_0402_12: CLABCONF0: =SB-UCMIMX8PLUS; P/N: 151B10400S
C6 = 100nF,_10V,_X7R,_10%,_0402_14: CLABCONF0: =SB-UCMIMX8PLUS; P/N: 151B10400S
C7 = 100nF,_10V,_X7R,_10%,_0402_3: CLABCONF0: =SB-UCMIMX8PLUS; P/N: 151B10400S
C8 = 100nF,_10V,_X7R,_10%,_0402_5: CLABCONF0: =SB-UCMIMX8PLUS; P/N: 151B10400S
C9 = 100nF,_10V,_X7R,_10%,_0402_7: CLABCONF0: =SB-UCMIMX8PLUS; P/N: 151B10400S
C10 = 100nF,_10V,_X7R,_10%,_0402_11: CLABCONF0: =SB-UCMIMX8PLUS; P/N: 151B10400S
C11 = 100nF,_10V,_X7R,_10%,_0402: CLABCONF0: =SB-UCMIMX8PLUS; P/N: 151B10400S
C12 = 100nF,_10V,_X7R,_10%,_0402_2: CLABCONF0: =SB-UCMIMX8PLUS; P/N: 151B10400S
C13 = 100nF,_10V,_X7R,_10%,_0402_8: CLABCONF0: =SB-UCMIMX8PLUS; P/N: 151B10400S
C21 = 100nF,_10V,_X7R,_10%,_0402_10: CLABCONF0: =SB-UCMIMX8PLUS; P/N: 151B10400S
C224 = 100nF,_10V,_X7R,_10%,_0402_4: CLABCONF0: =SB-UCMIMX8PLUS; P/N: 151B10400S
C225 = 100nF,_10V,_X7R,_10%,_0402_13: CLABCONF0: =SB-UCMIMX8PLUS; P/N: 151B10400S
C340 = 10uF_10V_20%_0402_3: CLABCONF0: =SB-UCMIMX8PLUS
C341 = 10uF_10V_20%_0402_5: CLABCONF0: =SB-UCMIMX8PLUS
C342 = 10uF_10V_20%_0402_1: CLABCONF0: =SB-UCMIMX8PLUS
C343 = 10uF_10V_20%_0402_6: CLABCONF0: =SB-UCMIMX8PLUS
C344 = 10uF_10V_20%_0402: CLABCONF0: =SB-UCMIMX8PLUS
C345 = 10uF_10V_20%_0402_2: CLABCONF0: =SB-UCMIMX8PLUS
C346 = 10uF_10V_20%_0402_4: CLABCONF0: =SB-UCMIMX8PLUS
E5 = HDR_1x2_100MIL_TH_JUMPER_2: CLABCONF0: DNP
E19 = HDR_1x2_100MIL_TH_JUMPER_1: CLABCONF0: =SB-UCMIMX8PLUS
E14 E20 = HDR_1x2_100MIL_TH_JUMPER: CLABCONF0: =SB-UCMIMX8PLUS
P1 = Hirose_DF40C-100DP-0.4V: CLABCONF0: = SB-UCMIMX8PLUS; P/N: 182K10005S
P2 = Hirose_DF40C-100DP-0.4V: CLABCONF0: =SB-UCMIMX8PLUS; P/N: 182K10005S
R182 = 0R,_0402_0_9: CLABCONF0: =SB-UCMIMX8PLUS; P/N: 161C00005S
R183 R203 = 0R,_0402_0_7: CLABCONF0: =SB-UCMIMX8PLUS; P/N: 161C00005S
R184 = 0R,_0402_0_3: CLABCONF0: =SB-UCMIMX8PLUS; P/N: 161C00005S
R185 R242 = 0R,_0402_0_2: CLABCONF0: =SB-UCMIMX8PLUS; P/N: 161C00005S
R186 = 0R,_0402_0_8: CLABCONF0: =SB-UCMIMX8PLUS; P/N: 161C00005S
R187 R204 = 0R,_0402_0_6: CLABCONF0: DNP; P/N: 161C00005S
R191 R202 = 0R,_0402_0: CLABCONF0: =SB-UCMIMX8PLUS; P/N: 161C00005S
R193 = 0R,_0402_0_1: CLABCONF0: DNP; P/N: 161C00005S
R194 R238 = 0R,_0402_0_4: CLABCONF0: DNP; P/N: 161C00005S
R195 = 0R,_0402_0_5: CLABCONF0: =SB-UCMIMX8PLUS; P/N: 161C00005S
SW5-SW7 = TACT_SW_6x6mm_SMT: CLABCONF0: =SB-UCMIMX8PLUS
C60 = Cap.,10uF,6.3V,0603,X5R: CLABCONF0: = SB-UCMIMX8PLUS
C34 C61 = 100nF,_10V,_X7R,_10%,_0402_1: CLABCONF0: = SB-UCMIMX8PLUS
C33 C66 = 100nF,_10V,_X7R,_10%,_0402: CLABCONF0: = SB-UCMIMX8PLUS
D1 = BAT54C: CLABCONF0: = SB-UCMIMX8PLUS
P6 = Con_0.,1GBit_RJ45,_short: CLABCONF0: = SB-UCMIMX8PLUS
R46 = 475R_1%,_0402_1: CLABCONF0: = SB-UCMIMX8PLUS
R47 = 475R_1%,_0402: CLABCONF0: = SB-UCMIMX8PLUS
C127 = 22uF,25V,_0805: CLABCONF0: =SB-UCMIMX8PLUS
C176 = 100nF,_10V,_X7R,_10%,_0402_5: CLABCONF0: =SB-UCMIMX8PLUS; Group: LAN2
C338 = 100nF,_10V,_X7R,_10%,_0402_7: CLABCONF0: =SB-UCMIMX8PLUS
C339 = 100nF,_10V,_X7R,_10%,_0402_9: CLABCONF0: =SB-UCMIMX8PLUS
C351 = 100nF,_10V,_X7R,_10%,_0402_13: CLABCONF0: =SB-UCMIMX8PLUS
C354 = 100nF,_10V,_X7R,_10%,_0402_14: CLABCONF0: =SB-UCMIMX8PLUS
C733 = 22uF,25V,_0805_1: CLABCONF0: =SB-UCMIMX8PLUS
C774 = 100nF,_10V,_X7R,_10%,_0402_2: CLABCONF0: =SB-UCMIMX8PLUS; P/N: 151C10500S
C775 = 100nF,_10V,_X7R,_10%,_0402_1: CLABCONF0: =SB-UCMIMX8PLUS; P/N: 151C10500S
C777 = 100nF,_10V,_X7R,_10%,_0402: CLABCONF0: =SB-UCMIMX8PLUS; P/N: 151C10500S
C778 = 100nF,_10V,_X7R,_10%,_0402_6: CLABCONF0: =SB-UCMIMX8PLUS; P/N: 151C10500S
C779 = 100nF,_10V,_X7R,_10%,_0402_12: CLABCONF0: =SB-UCMIMX8PLUS; P/N: 151C10500S
C780 = 100nF,_10V,_X7R,_10%,_0402_10: CLABCONF0: =SB-UCMIMX8PLUS; P/N: 151C10500S
C831 = 100nF,_10V,_X7R,_10%,_0402_15: CLABCONF0: =SB-UCMIMX8PLUS
C890 = 100nF,_10V,_X7R,_10%,_0402_8: CLABCONF0: =SB-UCMIMX8PLUS
C51 C103 C891 = 100nF,_10V,_X7R,_10%,_0402_3: CLABCONF0: =SB-UCMIMX8PLUS
C892 = 100nF,_10V,_X7R,_10%,_0402_11: CLABCONF0: =SB-UCMIMX8PLUS
C91 C893 = 100nF,_10V,_X7R,_10%,_0402_4: CLABCONF0: =SB-UCMIMX8PLUS
J3 = USB3_TYPEA_CONNECTER_0: CLABCONF0: =SB-UCMIMX8PLUS
J5 = USBTypeC_Receptacle_TOPMount_2: CLABCONF0: =SB-UCMIMX8PLUS; P/N: 180K02401S
L17-L24 L59-L63 = ESD_CHOKE_DIFFx2_10: CLABCONF0: =SB-UCMIMX8PLUS; P/N: 142D11801S
Q25 = N-MOSFET,NDS335N,100mOhm@2.5V: CLABCONF0: = SB-UCMIMX8PLUS
R84 R172 = 10K,1%,0402,1_16W_1: CLABCONF0: =SB-UCMIMX8PLUS
R236 = RESISTOR: CLABCONF0: =SB-UCMIMX8PLUS; P/N: 161C10045S
R237 = 10M,5%,0402,1_16W: CLABCONF0: =SB-UCMIMX8PLUS
R229 R241 = 10K,1%,0402,1_16W_0: CLABCONF0: =SB-UCMIMX8PLUS
R319 = 1M_,5%,_0402: CLABCONF0: =SB-UCMIMX8PLUS; P/N: 161C10021S
R320 = 1M_,5%,_0402_1: CLABCONF0: =SB-UCMIMX8PLUS; P/N: 161C10021S
R323 = 100K,_1%,_0402,_1_16W: CLABCONF0: =SB-UCMIMX8PLUS; P/N: 161C20031S
R324 = 100K,_1%,_0402,_1_16W_3: CLABCONF0: =SB-UCMIMX8PLUS; P/N: 161C20031S
R887 = 100K,_1%,_0402,_1_16W_4: CLABCONF0: =SB-UCMIMX8PLUS; P/N: 161C20031S
R888 = 10K,1%,0402,1_16W: CLABCONF0: DNP
R889 = 100K,_1%,_0402,_1_16W_5: CLABCONF0: =SB-UCMIMX8PLUS; P/N: 161C20031S
R890 = 100K,_1%,_0402,_1_16W_2: CLABCONF0: =SB-UCMIMX8PLUS; P/N: 161C20031S
R891 = 10K,1%,0402,1_16W_2: CLABCONF0: =SB-UCMIMX8PLUS
R892 = 0R,_0402_4: CLABCONF0: DNP
R893 = 0R,_0402_3: CLABCONF0: =SB-UCMIMX8PLUS
R894 = 0R,_0402_2: CLABCONF0: DNP
R72 R895 = 0R,_0402_1: CLABCONF0: DNP
R896 = 0R,_0402: CLABCONF0: DNP
R897 = 100K,_1%,_0402,_1_16W_1: CLABCONF0: =SB-UCMIMX8PLUS; P/N: 161C20031S
R41 R915 = 0R,_0402_5: CLABCONF0: =SB-UCMIMX8PLUS
U34 U43 = RT9703,3A_Power_switch+FLG: CLABCONF0: =SB-UCMIMX8PLUS
U36 = USB2_0.0_mux: CLABCONF0: =SB-UCMIMX8PLUS; P/N: 116A72220S
U39 = PCIE_Mux_Demux_2_1_2: CLABCONF0: =SB-UCMIMX8PLUS; P/N: 116A24123S
U42 = TI_HD3SS3220: CLABCONF0: =SB-UCMIMX8PLUS
C28 C38 C39 C45 = 1uF,X5R,6.3V,0402: CLABCONF0: = SB-UCMIMX8PLUS
C29 = 220pF,50V,NPO,0603_2: CLABCONF0: = SB-UCMIMX8PLUS
C30 C888 = 10uF_10V_20%_0402: CLABCONF0: = SB-UCMIMX8PLUS
C31 = 100nF,_10V,_X7R,_10%,_0402_4: CLABCONF0: = SB-UCMIMX8PLUS
C32 C886 = 10uF_10V_20%_0402_1: CLABCONF0: = SB-UCMIMX8PLUS
C35 C887 = 10uF_10V_20%_0402_2: CLABCONF0: = SB-UCMIMX8PLUS
C36 C889 = 10uF_10V_20%_0402_3: CLABCONF0: = SB-UCMIMX8PLUS
C37 = 100nF,_10V,_X7R,_10%,_0402_2: CLABCONF0: = SB-UCMIMX8PLUS
C40 C41 = 100uF,_6.3V,_X5R,_20%,_1210: CLABCONF0: = SB-UCMIMX8PLUS; P/N: 151B10730S
C42 = 220pF,50V,NPO,0603_1: CLABCONF0: = SB-UCMIMX8PLUS
C43 = 220pF,50V,NPO,0603: CLABCONF0: = SB-UCMIMX8PLUS
C44 = 100nF,_10V,_X7R,_10%,_0402_3: CLABCONF0: = SB-UCMIMX8PLUS
C46 C47 = 33pF,50V,NPO,10%,0402_0: CLABCONF0: DNP
C48 = 10nF,_25V,_X7R,_10%,_0402_1: CLABCONF0: = SB-UCMIMX8PLUS
C49 = 10nF,_25V,_X7R,_10%,_0402: CLABCONF0: = SB-UCMIMX8PLUS
C50 = 100pF,_50V,_NPO,_5%,_0402: CLABCONF0: = SB-UCMIMX8PLUS
C68 = 270pF,_50V,_X7R,_5%,_0402: CLABCONF0: =SB-UCMIMX8PLUS
C793 = 15pF,_50V,_NPO,_5%,_0402: CLABCONF0: =SB-UCMIMX8PLUS; P/N: 151B10400S
J6-J8 = AUDIO_JACK_3.5mm,_no_sw_0.,_SMT: CLABCONF0: =SB-UCMIMX8PLUS
P25 = TOSLINK_TX: CLABCONF0: =SB-UCMIMX8PLUS; P/N: 138E10030
P27 = RCA: CLABCONF0: =SB-UCMIMX8PLUS; P/N: 180K00401
R16 = 47K,_0402_1: CLABCONF0: = SB-UCMIMX8PLUS; P/N: 161C68001S
R17 = 10K,1%,0402,1_16W_1: CLABCONF0: = SB-UCMIMX8PLUS
R18 = 47K,_0402: CLABCONF0: = SB-UCMIMX8PLUS
R19 = 47K,_0402_2: CLABCONF0: = SB-UCMIMX8PLUS
R20 = 33R,5%,0402,1_16W_0: CLABCONF0: = SB-UCMIMX8PLUS
R21 = 5.62K_1%,0402_3: CLABCONF0: = SB-UCMIMX8PLUS
R22 = 5.62K_1%,0402_1: CLABCONF0: = SB-UCMIMX8PLUS
R23 = 0R,_0402_0_4: CLABCONF0: = SB-UCMIMX8PLUS
R24 = 0R,_0402_0_2: CLABCONF0: DNP
R25 = 5.62K_1%,0402: CLABCONF0: = SB-UCMIMX8PLUS
R26 = 5.62K_1%,0402_2: CLABCONF0: = SB-UCMIMX8PLUS
R27 = 47K,_0402_3: CLABCONF0: = SB-UCMIMX8PLUS
R28 = 0R,_0402_0_3: CLABCONF0: = SB-UCMIMX8PLUS
R31 = 10K,1%,0402,1_16W: CLABCONF0: = SB-UCMIMX8PLUS
R32 = 100R,1%,0402,1_16W_1: CLABCONF0: = SB-UCMIMX8PLUS
R33 = 100R,1%,0402,1_16W_2: CLABCONF0: = SB-UCMIMX8PLUS
R34 = 100R,1%,0402,1_16W: CLABCONF0: = SB-UCMIMX8PLUS
R35 = 220R,5%,0402,1_16W: CLABCONF0: = SB-UCMIMX8PLUS
R99 = 0R,_0402_0: CLABCONF0: DNP
R139 = 0R,_0402_0_1: CLABCONF0: DNP
U10 = TSC2046_2: CLABCONF0: = SB-UCMIMX8PLUS; P/N: 117A10010S
U11 = 74LCX04_sgl_gate_TSSOP-14: CLABCONF0: = SB-UCMIMX8PLUS
X1 = TMP_0: CLABCONF0: DNP; P/N: 141B12604I
C89 = 100nF,_10V,_X7R,_10%,_0402_5: CLABCONF0: =SB-UCMIMX8PLUS
C53 C90 = 100nF,_10V,_X7R,_10%,_0402: CLABCONF0: =SB-UCMIMX8PLUS
C54 C192 = 100nF,_10V,_X7R,_10%,_0402_1: CLABCONF0: =SB-UCMIMX8PLUS
C186 C193 = 100nF,_10V,_X7R,_10%,_0402_2: CLABCONF0: =SB-UCMIMX8PLUS
C367 C368 C371 C373 = 100nF,_10V,_X7R,_10%,_0402_0: CLABCONF0: =SB-UCMIMX8PLUS
C760 = 4.7uF_0402_10V_20%_1: CLABCONF0: = SB-UCMIMX8PLUS
C761 = 4.7uF_0402_10V_20%: CLABCONF0: = SB-UCMIMX8PLUS
D2 D10 D14 = BAT54WS_0: CLABCONF0: =SB-UCMIMX8PLUS
D12 = BAT54WS_0: CLABCONF0: DNP
P4 = Terminal,_5P,_3.81mm,_RA: CLABCONF0: = SB-UCMIMX8PLUS
P7 = HDR_2x5_100MIL_TH: CLABCONF0: =SB-UCMIMX8PLUS
P10 = HDR_2x5_100MIL_SMT: CLABCONF0: =SB-UCMIMX8PLUS
P20 P21 = HDR_2x17_100MIL_SMT: CLABCONF0: =SB-UCMIMX8PLUS
Q27 = N-MOSFET,NDS335N,100mOhm@2.5V: CLABCONF0: DNP
Q28 = P-MOSFET,3A,20V,110mOhm@-1.8V: CLABCONF0: DNP
R51 = 0R,_0402_1_21: CLABCONF0: =SB-UCMIMX8PLUS
R77 = 0R,_0402_1_16: CLABCONF0: DNP
R78 = 0R,_0402_1_27: CLABCONF0: =SB-UCMIMX8PLUS
R86 = 0R,_0402_1_1: CLABCONF0: DNP
R130 = 0R,_0402_1_2: CLABCONF0: =SB-UCMIMX8PLUS
R155 = 0R,_0402_1_24: CLABCONF0: DNP
R156 = 0R,_0402_1_12: CLABCONF0: =SB-UCMIMX8PLUS
R157 = 2.2K,5%,0402.1_16W_1: CLABCONF0: =SB-UCMIMX8PLUS
R158 = 0R,_0402_1_20: CLABCONF0: =SB-UCMIMX8PLUS
R159 = 0R,_0402_1_17: CLABCONF0: DNP
R160 = 4_0.75K,1%,0402,1_16W_3: CLABCONF0: =SB-UCMIMX8PLUS
R166 = 0R,_0402_1_5: CLABCONF0: DNP
R167 = 0R,_0402_1_22: CLABCONF0: DNP
R168 = 0R,_0402_1_3: CLABCONF0: =SB-UCMIMX8PLUS
R174 = 0R,_0402_1_23: CLABCONF0: =SB-UCMIMX8PLUS
R177 = 0R,_0402_1_8: CLABCONF0: =SB-UCMIMX8PLUS
R178 = 0R,_0402_1_7: CLABCONF0: =SB-UCMIMX8PLUS
R179 = 0R,_0402_1_25: CLABCONF0: =SB-UCMIMX8PLUS
R181 = 0R,_0402_1_14: CLABCONF0: =SB-UCMIMX8PLUS
R188 = 4_0.75K,1%,0402,1_16W_1: CLABCONF0: =SB-UCMIMX8PLUS
R189 = 4_0.75K,1%,0402,1_16W_2: CLABCONF0: =SB-UCMIMX8PLUS
R190 = 4_0.75K,1%,0402,1_16W: CLABCONF0: =SB-UCMIMX8PLUS
R192 = 0R,_0402_1_10: CLABCONF0: =SB-UCMIMX8PLUS
R196 = 0R,_0402_1_26: CLABCONF0: =SB-UCMIMX8PLUS
R197 = 0R,_0402_1_19: CLABCONF0: =SB-UCMIMX8PLUS
R198 = 0R,_0402_1_18: CLABCONF0: =SB-UCMIMX8PLUS
R199 = 0R,_0402_1_4: CLABCONF0: =SB-UCMIMX8PLUS
R200 = 0R,_0402_0_1: CLABCONF0: =SB-UCMIMX8PLUS; P/N: 161C00005S
R205 = 0R,_0402_0_3: CLABCONF0: DNP; P/N: 161C00005S
R228 = 0R,_0402_1_11: CLABCONF0: =SB-UCMIMX8PLUS
R230 = 0R,_0402_1_13: CLABCONF0: =SB-UCMIMX8PLUS
R231 = 0R,_0402_1_15: CLABCONF0: =SB-UCMIMX8PLUS
R75 R232 = 2.2K,5%,0402.1_16W: CLABCONF0: =SB-UCMIMX8PLUS
R233 = 10K,1%,0402,1_16W: CLABCONF0: =SB-UCMIMX8PLUS
R234 = 0R,_0402_0_5: CLABCONF0: DNP; P/N: 161C00005S
R235 = 10K,1%,0402,1_16W_0_2: CLABCONF0: =SB-UCMIMX8PLUS
R321 = 10K,1%,0402,1_16W_0_1: CLABCONF0: =SB-UCMIMX8PLUS
R325 = 10K,1%,0402,1_16W_0_4: CLABCONF0: =SB-UCMIMX8PLUS
R330 = 10K,1%,0402,1_16W_0: CLABCONF0: DNP
R332 = 60.4R_1%,_0402_3: CLABCONF0: =SB-UCMIMX8PLUS
R333 = 60.4R_1%,_0402: CLABCONF0: =SB-UCMIMX8PLUS
R342 = 0R,_0402_1_9: CLABCONF0: DNP
R343 = 60.4R_1%,_0402_1: CLABCONF0: =SB-UCMIMX8PLUS
R346 = 60.4R_1%,_0402_2: CLABCONF0: =SB-UCMIMX8PLUS
R347 = 0R,_0402_1_6: CLABCONF0: DNP
R362 = 10K,1%,0402,1_16W_0_5: CLABCONF0: DNP
R363 = 10K,1%,0402,1_16W_0_3: CLABCONF0: DNP
R364 = 1M_,5%,_0402: CLABCONF0: DNP; P/N: 161C10021S
RN17 = RN,10K,8P4R@0805: CLABCONF0: =SB-UCMIMX8PLUS
U14 = TXB0104_0: CLABCONF0: =SB-UCMIMX8PLUS; P/N: 116A10030S
U35 = PCA9555_1: CLABCONF0: =SB-UCMIMX8PLUS
U37 = TXS0102_0: CLABCONF0: =SB-UCMIMX8PLUS; P/N: 116A01020S
U58 U59 = ATA6563: CLABCONF0: =SB-UCMIMX8PLUS; P/N: 116A00380S
C52 = 10uF,6.3V,0603,20%X5R: CLABCONF0: =SB-UCMIMX8PLUS
C185 C187 C188 = 1uF,X5R,6.3V,0402: CLABCONF0: =SB-UCMIMX8PLUS
C278 = 1uF,X5R,6.3V,0402: CLABCONF0: =SB-UCMIMX8PLUS; P/N: 151D10510S
D7 = ZENER_24V_500mW_SOD-123: CLABCONF0: DNP
L8 = INC_DELTA_SI43-100,_10uH: CLABCONF0: =SB-UCMIMX8PLUS; CLABCONF1: <null>
P22 = FPC_Connector_0: CLABCONF0: =SB-UCMIMX8PLUS; P/N: 182P03002S
P45 = FPC_Connector_4: CLABCONF0: =SB-UCMIMX8PLUS; P/N: 182P00802S
R36 = 2.2R,5%,0402,1_16W: CLABCONF0: =SB-UCMIMX8PLUS; P/N: 161C00005S
R39 = 2.2R,5%,0402,1_16W_1: CLABCONF0: =SB-UCMIMX8PLUS; P/N: 161C06R25S
R83 = 0R,_0402_2: CLABCONF0: =SB-UCMIMX8PLUS
R138 = 0R,_0402_4: CLABCONF0: =SB-UCMIMX8PLUS
R210 = 0R,_0402_1: CLABCONF0: =SB-UCMIMX8PLUS
R211 = 0R,_0402_3: CLABCONF0: DNP
R221 = 0R,_0402: CLABCONF0: =SB-UCMIMX8PLUS
U15 = AIC1647_0: CLABCONF0: =SB-UCMIMX8PLUS; P/N: 123C40000S
U32 = IP4220CZ6_0: CLABCONF0: =SB-UCMIMX8PLUS

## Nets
1V8_PER: C89.1 C91.1 P10.2 R72.1 R77.2 R86.2 R157.1 R232.1 U14.1(VCCA) U37.3(VCCA) ; also on sheet 1 2 12 13 15
3V3_PER: C30.1 C31.1 C32.1 C33.1 C34.1 C35.1 C36.1 C37.1 C90.1 C103.1 C176.2 C185.1 C186.1 C367.1 C373.1 C780.2 C793.1 C887.1 C889.1 C890.1 C891.1 C892.1 C893.1 E14.1 P10.1 P20.7 P25.2(VCC) P45.3 R78.2 R83.2 R138.1 R159.2 R160.1 R166.2 R167.2 R182.1 R188.1 R191.1 R200.2 R210.1 R235.1 R242.2 R319.2 R320.2 R364.2 R897.1 U10.3(DCVDD) U10.5(DBVDD) U10.12(HPVDD) U10.18(AVDD) U11.14(VCC) U14.14(VCCB) U32.5(VBUS) U36.9(VCC) U37.7(VCCB) U39.5(VDD) U39.8(VDD) U39.13(VDD) U39.18(VDD) U39.20(VDD) U39.30(VDD) U39.40(VDD) U39.42(VDD) U42.8(VCC33) U58.5(VIO) U59.5(VIO) ; also on sheet 1 2 3 4 12 13 14 15
5V0_PER: C368.2 C371.2 C777.2 C778.2 C779.2 C831.1 C886.1 C888.1 P20.6 R887.1 R888.1 R889.1 R890.1 R891.1 U34.6(Vin) U34.7(Vin) U42.30(VDD5) U43.6(Vin) U43.7(Vin) U58.3(VCC) U59.3(VCC) ; also on sheet 3 4 13
AGND: C29.1 C34.2 C35.2 C36.2 C37.2 C42.2 C43.2 C44.2 C45.2 J6.1(COM) J7.1(COM) J8.1(COM) R18.2 R19.2 R25.1 R26.1 R27.2 R99.2 U10.15(HPGND) U10.19(AGND) U10.29(PAD) ; also on sheet 15
GND: C2.2 C3.2 C4.2 C5.2 C6.2 C7.2 C8.2 C9.2 C10.2 C11.2 C12.2 C13.2 C21.2 C30.2 C31.2 C32.2 C33.2 C46.1 C47.1 C50.2 C51.2 C52.2 C53.2 C54.1 C60.2 C61.2 C66.2 C68.2 C89.2 C90.2 C91.2 C103.2 C127.2 C176.1 C185.2 C186.2 C187.1 C188.2 C192.1 C193.2 C224.2 C225.1 C278.2 C340.2 C341.2 C342.2 C343.1 C344.2 C345.2 C346.2 C367.2 C368.1 C371.1 C373.2 C733.2 C760.2 C761.2 C774.1 C775.1 C777.1 C778.1 C779.1 C780.1 C793.2 C831.2 C886.2 C887.2 C888.2 C889.2 C890.2 C891.2 C892.2 C893.2 J3.4(GND) J3.7(GND) J3.SH1 J3.SH2 J5.A1(GND0) J5.A12(GND1) J5.B1(GND2) J5.B12(GND3) J5.Sh1 J5.Sh2 J5.Sh3 J5.Sh4 L17.5(GND) L17.6(GND) L18.5(GND) L18.6(GND) L19.5(GND) L19.6(GND) L20.5(GND) L20.6(GND) L21.5(GND) L21.6(GND) L22.5(GND) L22.6(GND) L23.5(GND) L23.6(GND) L24.5(GND) L24.6(GND) L59.5(GND) L59.6(GND) L60.5(GND) L60.6(GND) L61.5(GND) L61.6(GND) L62.5(GND) L62.6(GND) L63.5(GND) L63.6(GND) P1.4 P1.10 P1.20 P1.40 P1.54 P1.64 P1.78 P1.88 P2.10 P2.16 P2.22 P2.28 P2.34 P2.40 P2.46 P2.54 P2.72 P2.82 P4.3 P6.S1(SHIELD) P6.S2(SHIELD) P7.4 P7.6 P10.10 P20.31 P20.32 P21.6 P21.9 P22.6 P22.9 P22.12 P22.15 P22.18 P22.21 P22.22 P22.24 P22.29 P22.30 P22.NC1 P22.NC2 P25.1(GND) P25.4(NC) P25.5(NC) P27.1(SHIELD) P27.3(SHIELD) P27.4(SHIELD) P45.1 P45.8 P45.NC1 P45.NC2 Q25.2(S) Q27.2(S) R34.1 R35.2 R36.2 R46.2 R47.2 R51.1 R75.2 R84.1 R99.1 R172.2 R183.2 R184.2 R194.2 R233.2 R241.1 R321.1 R323.2 R324.2 R325.1 R892.1 R893.1 R896.2 RN17.2(RB1) RN17.3(RC1) RN17.4(RD1) U10.4(DGND) U10.25(MODE) U10.26(CSB) U11.7(GND) U14.7(GND) U15.2(GND) U32.2(GND) U34.4(GND) U35.9(VSS) U35.25(CPAD) U36.4(GND) U37.2(GND) U39.1(GND) U39.4(GND) U39.10(GND) U39.14(GND) U39.17(GND) U39.19(XSD23) U39.21(GND) U39.39(GND) U39.41(XSD01) U39.43(EPAD) U42.13(GND) U42.28(GND) U42.29(EN_CC#) U42.Tpad(TPAD) U43.4(GND) U58.2(GND) U59.2(GND) X1.2 X1.4 ; also on sheet 1 2 3 4 12 13 14 15
VCC_RTC: P1.93 ; also on sheet 13
VDD_EXP: C193.1 Q28.3(D) R242.1 U35.21(VDD)
A_IN: C48.2 R32.2
ADCLRC: R23.1 R24.1 U10.11(ADCLRC)
ALT_BOOT: P1.90 R186.1
AMP_IN: R31.2 R32.1 U11.3(I)
AMP_OUT: R31.1 U11.1(I) U11.4(12)
AMP_SPDIF_RX: R139.2 U11.2(12)
AMPR: C28.2 R17.1
AUD_VMID: C44.1 C45.1 U10.20(VMID)
AUDIO_IN_DIG: C48.1 C68.1 P27.2(CENTER) R34.2
AUDIO_OUT_DIG: C50.1 P25.3(IN) R33.2 R35.1
CAN1_CAP: C760.1 R332.1 R333.2
CAN1_H: P4.1 R332.2 U58.7(CANH)
CAN1_L: P4.2 R333.1 U58.6(CANL)
CAN1_RX/SAI2_TXC: P1.51 P21.12 U58.4(RXD)
CAN1_STBY: R321.2 R342.2 U58.8(STBY)
CAN1_TX/SAI2_RXC: P1.53 P21.14 U58.1(TXD)
CAN2_CAP: C761.1 R343.1 R346.2
CAN2_H: P4.4 R343.2 U59.7(CANH)
CAN2_L: P4.5 R346.1 U59.6(CANL)
CAN2_RX/SAI2_MCLK: P1.49 P21.10 U59.4(RXD)
CAN2_STBY: R325.2 R347.2 U59.8(STBY)
CAN2_TX/SAI2_TXD0: P1.33 P21.8 U59.1(TXD)
CARRIER_3V3_GPIO0_0: R156.2 U35.1(I/O0.0)
CARRIER_3V3_GPIO0_1: R168.2 U35.2(I/O0.1)
CARRIER_3V3_GPIO0_2: R158.2 U35.3(I/O0.2)
CARRIER_3V3_GPIO0_3: R174.2 U35.4(I/O0.3)
CARRIER_3V3_GPIO0_4: R196.2 U35.5(I/O0.4)
CARRIER_3V3_GPIO0_5: R197.2 U35.6(I/O0.5)
CARRIER_3V3_GPIO0_6: R177.2 U35.7(I/O0.6)
CARRIER_3V3_GPIO0_7: R199.2 U35.8(I/O0.7)
CARRIER_3V3_GPIO1_0: R178.2 U35.10(I/O1.0)
CARRIER_3V3_GPIO1_1: R179.2 U35.11(I/O1.1)
CARRIER_3V3_GPIO1_2: R181.2 U35.12(I/O1.2)
CARRIER_3V3_GPIO1_3: R198.2 U35.13(I/O1.3)
CARRIER_3V3_GPIO1_4: R192.2 U35.14(I/O1.4)
CARRIER_3V3_GPIO1_5: R228.2 U35.15(I/O1.5)
CARRIER_3V3_GPIO1_6: R230.2 U35.16(I/O1.6)
CARRIER_3V3_GPIO1_7: R231.2 U35.17(I/O1.7)
CDC_BCLK: R20.2 U10.7(BCLK)
CODEC_XTALIN: C46.2 R28.1 U10.1(XTI/MCLK) X1.1(Y1)
CODEC_XTALOUT: C47.2 U10.2(XTO) X1.3(Y3)
CSI1_B_FLASH_OUT: R181.1 ; also on sheet 2
CSI1_B_RST: R179.1 ; also on sheet 2
CSI1_B_TRG: R198.1 ; also on sheet 2
CSI1_PWR_DWN_B: R178.1 ; also on sheet 2
CSI2_B_FLASH_OUT: R231.1 ; also on sheet 1
CSI2_B_RST: R228.1 ; also on sheet 1
CSI2_B_TRG: R230.1 ; also on sheet 1
CSI2_PWR_DWN_B: R192.1 ; also on sheet 1
DRP_ADDR: R890.2 R892.2 U42.22(ADDR)
DRP_CMODE: R888.2 U42.3(CURRENT_MODE)
DRP_DIR: R897.2 U42.11(DIR)
DRP_ENMUX_N: R893.2 U42.12(EN_MUX#)
DRP_ID: R887.2 R896.1 U42.27(ID)
DRP_RXN1: L22.2 U42.14(RX1N)
DRP_RXN2: L20.1 U42.18(RX2N)
DRP_RXP1: L22.1 U42.15(RX1P)
DRP_RXP2: L20.2 U42.19(RX2P)
DRP_TXN1: C339.2 U42.16(TX1N)
DRP_TXN2: C354.2 U42.20(TX2N)
DRP_TXP1: C338.2 U42.17(TX1P)
DRP_TXP2: C351.2 U42.21(TX2P)
DRP_VBUS_DET: R236.1 R237.2 U42.5(VBUS_DET)
DRP_VCFAULT_N: R891.2 R894.2 U42.24(VCONN_FAULT_N)
DSI1_CN: L61.2 P22.13
DSI1_CP: L61.1 P22.14
DSI1_N0: L59.2 P22.7
DSI1_N1: L60.2 P22.10
DSI1_N2: L62.2 P22.16
DSI1_N3: L63.2 P22.19
DSI1_P0: L59.1 P22.8
DSI1_P1: L60.1 P22.11
DSI1_P2: L62.1 P22.17
DSI1_P3: L63.1 P22.20
DSI_BCKLIGHT_FB: D7.2(ANODE) R41.2 U15.3(FB)
DSI_BCKLIGHT_IN: C51.1 C52.1 L8.1 R210.2 R229.1 U15.6(IN)
DSI_DISP_IOVCC: C54.2 C188.1 P22.27 R83.1
DSI_DISP_RESET: P22.26 R75.1 R196.1
DSI_DISP_VCI: C53.1 C187.2 P22.28 R138.2
DSI_LED_A: C278.1 D2.CATHODE D7.1(CATHODE) P22.4 U15.5(OVP)
DSI_LED_EN: R211.2 R229.2 U15.4(EN/PWM)
DSI_LED_K: P22.2 R39.1 R41.1
DSI_TOUCH_RESET: R197.1 R221.1
DSI_WLD_RES: R36.1 R39.2
DSI_WLD_SW: D2.ANODE L8.2 U15.1(LX)
EARC_N_HPD: P1.35 ; also on sheet 3
EARC_P_UTIL: P1.37 ; also on sheet 3
ECSPI2_MISO: P2.89 P21.22
ECSPI2_MOSI: P2.95 P21.28
ECSPI2_SCLK: P2.93 P21.26
ECSPI2_SS0: P2.91 P21.24
ENET1_INT/SAI2_RXFS: P2.88 P20.18
ENET1_MDC/SD1_CLK: P2.68 P20.15
ENET1_MDIO/SD1_CMD: P2.70 P20.17
ENET1_nRST/SAI2_TXFS: P2.76 P20.16
ENET1_RD0/SD1_DATA2: P2.41 P20.21
ENET1_RD1/SD1_DATA3: P2.43 P20.23
ENET1_RD2/SAI1_RXD6: P2.45 P20.25
ENET1_RD3/SAI1_RXD7: P2.47 P20.27
ENET1_RX_CTL/SAI1_TXFS: P2.53 P20.19
ENET1_RXC/SAI1_TXC: P2.55 P20.29
ENET1_TD0/SD1_DATA1: P2.59 P20.22
ENET1_TD1/SD1_DATA0: P2.61 P20.24
ENET1_TD2/SAI1_TXD2: P2.63 P20.26
ENET1_TD3/SAI1_TXD3: P2.65 P20.28
ENET1_TX_CTL/SAI1_TXD4: P2.67 P20.20
ENET1_TXC/SAI1_TXD5: P2.69 P20.30
ENET_TD2_BYPASS: P2.77 P21.27
ETH0_CT1: C60.1 C61.1 P6.P5(CT)
ETH0_GREEN_LED_CAT: P6.P11(LED1_C) R46.1
ETH0_LED_ACT/PHY1ADDRESS2: P2.83 P6.P12(LED1_A)
ETH0_LINK-LED_10_100: D1.1(ANODE1) P2.86
ETH0_LINK-LED_1000/INTSELECT: D1.2(ANODE2) P2.75
ETH0_MDI0N: P2.73 P6.P2(MDI0-)
ETH0_MDI0P: P2.74 P6.P1(MDI0+)
ETH0_MDI1N: P2.80 P6.P4(MDI1-)
ETH0_MDI1P: P2.78 P6.P3(MDI1+)
ETH0_MDI2N: P2.81 P6.P8(MDI2-)
ETH0_MDI2P: P2.79 P6.P7(MDI2+)
ETH0_MDI3N: P2.85 P6.P10(MDI3-)
ETH0_MDI3P: P2.84 P6.P9(MDI3+)
ETH0_YELLOW_LED_AN: D1.3(CATHODE) P6.P14(LED2_A)
ETH0_YELLOW_LED_CAT: P6.P13(LED2_C) R47.1
ETH1_CT2: C66.1 P6.P6(CT)
EXPANDER_A0: R166.1 RN17.5(RD2) U35.18(A0)
EXPANDER_A1: R167.1 RN17.6(RC2) U35.23(A1)
EXPANDER_A2: R159.1 RN17.7(RB2) U35.24(A2)
FLEXSPI_BOOT: E20.2 R191.2
G_Q27: Q27.1(G) R238.1
GPIO1_00: P1.59 P20.12 R342.1
GPIO1_01: P1.98 P20.14 R347.1
GPIO4_12/SAI1_TXD0: P2.60 P21.34 P45.6 U32.3(IO2)
HASW_EN: Q25.3(D) R320.1 U43.5(EN)
HASW_IP: R324.1 U43.8(IP)
HDMI_CEC: P1.85 P21.33 ; also on sheet 3
HDMI_DDC_SCL: P1.70 P21.29 ; also on sheet 3
HDMI_DDC_SDA: P1.63 P21.31 ; also on sheet 3
HDMI_HPD: P1.92 P21.25 ; also on sheet 3
HDMI_TX0N: P1.31 ; also on sheet 3
HDMI_TX0P: P1.29 ; also on sheet 3
HDMI_TX1N: P1.41 ; also on sheet 3
HDMI_TX1P: P1.39 ; also on sheet 3
HDMI_TX2N: P1.47 ; also on sheet 3
HDMI_TX2P: P1.45 ; also on sheet 3
HDMI_TXCN: P1.25 ; also on sheet 3
HDMI_TXCP: P1.23 ; also on sheet 3
HOSTA_USB_DN: J3.2(DN) L21.4
HOSTA_USB_DP: J3.3(DP) L21.3
HUB_OE: R241.2 U36.8(\\~{O}E)
I2C3_SCL: P1.94 P20.33 R205.2 U37.8(B1)
I2C3_SDA: P1.91 P20.34 R204.2 U37.1(B2)
I2C5_SCL/SAI5_RXD0: P1.100 P21.3 P45.4 R188.2 U32.6(IO4) ; also on sheet 2
I2C5_SDA/SAI5_MCLK: P1.96 P21.1 P45.5 R160.2 U32.4(IO3) ; also on sheet 2
I2C6_SCL: R202.1 R205.1 ; also on sheet 1 4
I2C6_SCL/SAI5_RXFS: P1.87 P21.2 R190.2 R202.2
I2C6_SDA: R203.1 R204.1 ; also on sheet 1 4
I2C6_SDA/SAI5_RXC: P1.89 P21.4 R189.2 R203.2
I2C_LS_OE: R86.1 R233.1 U37.6(OE)
I2S_LS_OE: R77.1 R84.2 U14.8(OE)
INT_EXP: R234.1 R235.2 U35.22(\\~{IN}T)
J_MOD_8: P7.8 R155.2
JTAG_HDR_2: P7.2 R130.2
JTAG_HDR_10: P7.10 R51.2
JTAG_MOD: P1.75 R155.1
JTAG_POWER: C192.2 D14.ANODE R72.2 R78.1 R130.1 R362.1 R363.1
JTAG_RST: D10.CATHODE D12.CATHODE P7.9 R330.2
JTAG_RST_PU: D14.CATHODE R330.1
JTAG_TCK: P1.73 P7.3
JTAG_TDI: P1.71 P7.7 R363.2
JTAG_TDO: P1.67 P7.5
JTAG_TMS: P1.65 P7.1 R362.2
LHPOUT: C41.1 J8.2(L) R19.1
LHPOUT_T: C41.2 U10.13(LHPOUT)
LIN_T: C39.2 C42.1 R22.1 R25.2
LLINEIN: J7.2(L) R22.2
LLINEIN_T: C39.1 U10.24(LLINEIN)
LVDS0_CLK_N: P1.82 ; also on sheet 4
LVDS0_CLK_P: P1.80 ; also on sheet 4
LVDS0_D0_N: P1.44 ; also on sheet 4
LVDS0_D0_P: P1.42 ; also on sheet 4
LVDS0_D1_N: P1.48 ; also on sheet 4
LVDS0_D1_P: P1.46 ; also on sheet 4
LVDS0_D2_N: P1.52 ; also on sheet 4
LVDS0_D2_P: P1.50 ; also on sheet 4
LVDS0_D3_N: P1.58 ; also on sheet 4
LVDS0_D3_P: P1.56 ; also on sheet 4
LVDS_DISP_RESET: R177.1 ; also on sheet 4
LVDS_TOUCH_RESET: R199.1 ; also on sheet 4
M2_I2C_SCL: R157.2 U37.5(A1) ; also on sheet 12
M2_I2C_SDA: R232.2 U37.4(A2) ; also on sheet 12
M2_I2S_CLK: U14.3(A2) ; also on sheet 12
M2_I2S_DIN: U14.4(A3) ; also on sheet 12
M2_I2S_DOUT: U14.2(A1) ; also on sheet 12
M2_I2S_WS: U14.5(A4) ; also on sheet 12
M2_USB3_SSRXN: U39.34(C0+) ; also on sheet 12
M2_USB3_SSRXP: U39.33(C0-) ; also on sheet 12
M2_USB3_SSTXN: U39.32(C1+) ; also on sheet 12
M2_USB3_SSTXP: U39.31(C1-) ; also on sheet 12
M2_USB_DN: U36.6(HSD2-) ; also on sheet 12
M2_USB_DP: U36.2(HSD2+) ; also on sheet 12
MIC_IN: C28.1 C29.2 J6.2(L) R16.2 R18.1
MICBIAS: R16.1 U10.21(MICBIAS)
MICIN: R17.2 U10.22(MICIN)
MIPI_CSI1_CLK_N: P2.2 ; also on sheet 2
MIPI_CSI1_CLK_P: P2.4 ; also on sheet 2
MIPI_CSI1_D0_N: P2.6 ; also on sheet 2
MIPI_CSI1_D0_P: P2.8 ; also on sheet 2
MIPI_CSI1_D1_N: P2.31 ; also on sheet 2
MIPI_CSI1_D1_P: P2.33 ; also on sheet 2
MIPI_CSI1_D2_N: P2.25 ; also on sheet 2
MIPI_CSI1_D2_P: P2.27 ; also on sheet 2
MIPI_CSI1_D3_N: P2.35 ; also on sheet 2
MIPI_CSI1_D3_P: P2.37 ; also on sheet 2
MIPI_CSI2_CLK_N: P2.12 ; also on sheet 1
MIPI_CSI2_CLK_P: P2.14 ; also on sheet 1
MIPI_CSI2_D0_N: P2.18 ; also on sheet 1
MIPI_CSI2_D0_P: P2.20 ; also on sheet 1
MIPI_CSI2_D1_N: P2.24 ; also on sheet 1
MIPI_CSI2_D1_P: P2.26 ; also on sheet 1
MIPI_CSI2_D2_N: P2.48 ; also on sheet 1
MIPI_CSI2_D2_P: P2.50 ; also on sheet 1
MIPI_CSI2_D3_N: P2.56 ; also on sheet 1
MIPI_CSI2_D3_P: P2.58 ; also on sheet 1
MIPI_DSI1_CLK_N: L61.3 P2.21
MIPI_DSI1_CLK_P: L61.4 P2.23
MIPI_DSI1_D0_N: L59.3 P2.1
MIPI_DSI1_D0_P: L59.4 P2.3
MIPI_DSI1_D1_N: L60.3 P2.15
MIPI_DSI1_D1_P: L60.4 P2.17
MIPI_DSI1_D2_N: L62.3 P2.5
MIPI_DSI1_D2_P: L62.4 P2.7
MIPI_DSI1_D3_N: L63.3 P2.11
MIPI_DSI1_D3_P: L63.4 P2.13
MIPI_FPC_RES: P45.7 R221.2 U32.1(IO1)
mPCIe_PERST: R156.1 ; also on sheet 12
MUX_USB3_SEL: E14.2 Q25.1(G) R172.1 R915.2 U39.9(SEL)
MUX_USB3_SSRXN: L17.2 U39.38(B0+)
MUX_USB3_SSRXP: L17.1 U39.37(B0-)
MUX_USB3_SSTXN: L18.2 U39.36(B1+)
MUX_USB3_SSTXP: L18.1 U39.35(B1-)
MUX_USB_DN: L21.1 U36.7(HSD1-)
MUX_USB_DP: L21.2 U36.1(HSD1+)
PB_ALT_BOOT: E19.1 R186.2 SW7.2 SW7.4
PB_RESET: R185.2 R193.2 SW6.2 SW6.4
PCIE_CLKREQ_B/I2C4_SCL: P2.90 P21.20 ; also on sheet 12
PCIE_REF_CLKN: P2.44 ; also on sheet 12
PCIE_REF_CLKP: P2.42 ; also on sheet 12
PCIE_RXN_N: P2.30 ; also on sheet 12
PCIE_RXN_P: P2.32 ; also on sheet 12
PCIE_TXN_N: P2.36 ; also on sheet 12
PCIE_TXN_P: P2.38 ; also on sheet 12
PHY_2V5: C224.1 P1.55 P10.4
PIMICPOWER_ON: E5.2 R194.1
PMIC_ON_REQ: P1.68 P10.5 ; also on sheet 13
PMIC_STBY_REQ: P1.66 P10.3
POR_B_3P3: D12.ANODE E5.1 P2.66 P10.7 R187.1 R193.1 ; also on sheet 13
PU_PWR_I2C6: R189.1 R190.1 R200.1
PWM1_OUT/SPDIF_EXT_CLK: P1.77 P20.5 R211.1
PWRBTN: P2.64 R195.1
Q27_Q28: Q27.3(D) Q28.1(G)
QSPI_BOOT_EN_3P3: E20.1 P1.95 P21.18
RESERVED1: P1.22 P10.6
RESERVED2: P1.17 P10.8
RHPOUT: C40.1 J8.3(R) R27.1
RHPOUT_T: C40.2 U10.14(RHPOUT)
RIN_T: C38.2 C43.1 R21.1 R26.2
RLINEIN: J7.3(R) R21.2
RLINEIN_T: C38.1 U10.23(RLINEIN)
S_Q28: Q28.2(S) R364.1
SAI3_MCLK: P1.30 P21.15 R28.2 U14.12(B2)
SAI3_RXC/UART2_CTS: P1.32 P21.19
SAI3_RXD/UART2_RTS: P1.28 P21.17 U10.10(ADCDAT) U14.11(B3)
SAI3_RXFS: P1.34 P21.23 R24.2
SAI3_TXC: P1.36 P21.13 R20.1
SAI3_TXD: P1.26 P21.11 U10.8(DACDAT) U14.13(B1)
SAI3_TXFS: P1.38 P21.21 R23.2 U10.9(DACLRC) U14.10(B4)
SD1_RESET_B: P2.62 P20.13
SD2_CLK: P2.96 ; also on sheet 14
SD2_CMD: P2.100 ; also on sheet 14
SD2_DATA0: P2.97 ; also on sheet 14
SD2_DATA1: P2.99 ; also on sheet 14
SD2_DATA2: P2.94 ; also on sheet 14
SD2_DATA3: P2.98 ; also on sheet 14
SD2_nCD: P2.92 ; also on sheet 14
SD2_nRST: P2.51 P21.16
SPDIF_OUT1C: C49.1 R33.1
SPDIF_RX: P1.79 R139.1 ; also on sheet 4
SPDIF_TX: C49.2 P1.81
SW_ALT_BOOT: E19.2 R182.2 SW7.1 SW7.3
SW_PWRBTN: R184.1 SW5.1 SW5.3
SW_RES: R183.1 SW6.1 SW6.3
SWPWRBTN: R187.2 R195.2 SW5.2 SW5.4
SYS_I2C_SCL: P1.99 P21.7 U10.28(SCLK) U35.19(SCL) U42.26(SCL) ; also on sheet 12 14
SYS_I2C_SDA: P1.97 P21.5 U10.27(SDIN) U35.20(SDA) U42.25(SDA) ; also on sheet 12 14
SYS_RST_PMIC: D10.ANODE P1.2 P10.9 R185.1 ; also on sheet 13
TCCAP_SSTXN1: C339.1 L19.2
TCCAP_SSTXN2: C354.1 L24.1
TCCAP_SSTXP1: C338.1 L19.1
TCCAP_SSTXP2: C351.1 L24.2
TCSW_EN: R319.1 U34.5(EN)
TCSW_FLG#: R894.1 U34.1(FLG)
TCSW_IP: R323.1 U34.8(IP)
TYPEC_CC1: J5.A5(CC1) U42.2(CC1)
TYPEC_CC2: J5.B5(CC2) U42.1(CC2)
TYPEC_DN: J5.A7(DN1) J5.B7(DN2) L23.3
TYPEC_DP: J5.A6(DP1) J5.B6(DP2) L23.4
TYPEC_SSRXN1: J5.B10(SSRXN1) L22.3
TYPEC_SSRXN2: J5.A10(SSRXN2) L20.4
TYPEC_SSRXP1: J5.B11(SSRXP1) L22.4
TYPEC_SSRXP2: J5.A11(SSRXP2) L20.3
TYPEC_SSTXN1: J5.A3(SSTXN1) L19.3
TYPEC_SSTXN2: J5.B3(SSTXN2) L24.4
TYPEC_SSTXP1: J5.A2(SSTXP1) L19.4
TYPEC_SSTXP2: J5.B2(SSTXP2) L24.3
UART1_RXD: P1.19 P20.11 ; also on sheet 14
UART1_TXD: P1.72 P20.9 ; also on sheet 14
UART2_RXD: P1.76 P20.3 ; also on sheet 14
UART2_TXD: P1.74 P20.1 ; also on sheet 14
UART3_RXD: P1.21 P20.4
UART3_TXD: P1.61 P20.2
UART4_RXD: P1.84 P20.10 ; also on sheet 14
UART4_TXD: P1.86 P20.8 ; also on sheet 14
UART_DEBUGSEL: R158.1 ; also on sheet 14
UCM_AVDD33_ETH: C225.2 C343.2 P1.62
USB1_DN: L23.2 P1.14
USB1_DP: L23.1 P1.12
USB1_RX_N: P1.8 U42.10(RXN)
USB1_RX_P: P1.6 U42.9(RXP)
USB1_SS_SEL/SAI1_MCLK: P2.52 P21.32 ; also on sheet 12
USB1_TCPC_nINT/SAI1_TXD7: P1.60 P21.30 R234.2 R238.2 R889.2 U42.23(INT_N)
USB1_TX_N: P1.18 U42.7(TXN)
USB1_TX_P: P1.16 U42.6(TXP)
USB1_TYPEC_EN_B/SD2_WP: P2.49 ; also on sheet 4
USB1_VBUS: C733.1 C774.2 C775.2 J5.A4(VBUS1) J5.A9(VBUS2) J5.B4(VBUS3) J5.B9(VBUS4) P1.24 R236.2 R237.1 U34.2(Vout) U34.3(Vout)
USB2_DN: P1.5 U36.5(D-)
USB2_DP: P1.3 U36.3(D+)
USB2_RX_N: P1.9 U39.2(A0+)
USB2_RX_P: P1.7 U39.3(A0-)
USB2_SEL: R915.1 U36.10(SEL)
USB2_TX_N: P1.15 U39.6(A1+)
USB2_TX_P: P1.13 U39.7(A1-)
USB2_VBUS: P1.1 R895.2
USB3_HOSTA_SSRXN: J3.5(SSRXN) L17.3
USB3_HOSTA_SSRXP: J3.6(SSRXP) L17.4
USB3_HOSTA_SSTXN: J3.8(SSTXN) L18.3
USB3_HOSTA_SSTXP: J3.9(SSTXP) L18.4
USB3_HOSTA_VBUS: C127.1 J3.1(VBUS) R895.1 U43.2(Vout) U43.3(Vout)
V_SOM: C2.1 C3.1 C4.1 C5.1 C6.1 C7.1 C8.1 C9.1 C10.1 C11.1 C12.1 C13.1 C21.1 C340.1 C341.1 C342.1 C344.1 C345.1 C346.1 P1.11 P1.27 P1.43 P1.57 P1.69 P1.83 P2.9 P2.19 P2.29 P2.39 P2.57 P2.71 P2.87 ; also on sheet 13 15

Not connected (* = marked no-connect by the designer): J5 A8(SBU1)* B8(SBU2)*; J6 3(R)*; P22 1* 3* 5* 23* 25*; P45 2*; R168 1*; R174 1*; RN17 1(RA1)* 8(RA2)*; U10 6(CLKOUT)* 16(LOUT)* 17(ROUT)*; U14 6(NC)* 9(NC)*; U39 11(A2+)* 12(A2-)* 15(A3+)* 16(A3-)* 22(C3-)* 23(C3+)* 24(C2-)* 25(C2+)* 26(B3-)* 27(B3+)* 28(B2-)* 29(B2+)*; U42 4(PORT)*; U43 1(FLG)*

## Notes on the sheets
sheet 6
- V-SOM decoupling capacitors
- A53 core debug
- Place close to UCM-iMX8M-Plus connectors
- M7 core debug
- SILKSCREEN: POR_B
- DNP
- DNP
- DNP
- SILKSCREEN: POWER
- SILKSCREEN: RESET
- DNP
- POR_B_3P3 to PCA9450: Power On reset output pin.
  Open drain output, external pull up resistor is near the SoC.
- SILKSCREEN: ALT_BOOT
- SILKSCREEN: FlexSPI_BOOT
sheet 7
- Ethernet connector
- SILKSCREEN:
  ETH0
- 100 Ohm
- 100 Ohm
- 100 Ohm
- 100 Ohm
sheet 8
- USB3.0 Type-C
- SILKSCREEN:
  Type-C (USB1)
- USB1_VBUS is isolated by 30K resistor on UCM
- DNP
- # 90-Ohm diff pairs
- DNP
- DNP
- # 90-Ohm diff pairs
- CURRENT_MODE -The
  pin has 250 K internal pull-down.
  900 mA - Low (Default)
  1.5 A - 500K PU to VDD5
  3.0 A - 10K PU to VDD5
- Pin 27 (ADDR):
  PU - I2C 7-bit address is 0x67.
  PD - I2C 7-bit address is 0x47.
- DNP
- 1.05A LIMIT
- USB3.0 HOST with MUX to M.2 KeyB
- # 90-Ohm differential pairs
- SILKSCREEN:
  M.2 USB3 Enable
- USB2_VBUS is isolated by 30K resistor on UCM
- DNP
- SILKSCREEN:
  USB3.0 (USB2)
- 90 ohm
- # 90-Ohm differential pairs
- # 90-Ohm differential pairs
- 1.05A LIMIT
sheet 9
- Audio Codec
- POWER CONSUMPTION:
  DBVDD = 1.5mA @ 3.3V (typ)
  DCVDD = 3.2mA @ 1.5V (typ) ==> assuming same current @ 3.3V
  HPVDD = 1.7mA @ 3.3V (typ)
  AVDD = 13.1mA @ 3.3V (typ)
  1.5+3.2+1.7+13.1=19.5mA @ 3.3V (typ):
  Assuming worst case is 50mA @ 3.3V
- SILKSCREEN:
  Mic IN
- Place C93 and C94
  ACAP to U10 pins 5 and 4
- Place C97 and C98
  ACAP to U10 pins 3 and 4
- Place C99 and C100
  ACAP to U10 pins 18 and 19
- Place C95 and C170
  ACAP to U10 pins 12 and 15
- I2C ADDRESS: 0b0011010 (0x1AH)
- SILKSCREEN:
  Audio IN
- CP
- DNP
- CP
- SILKSCREEN:
  Audio OUT
- Keep analog signals clear from other signals at least 30mills
  Analog signals list will be provided in separate doc
- DNP
- DNP
- Keep S1 close to U11
  S1 width at least 20 mil
- DNP
- 20mil
- 20mil
- DNP
- DNP
- SPDIF
- SILKSCREEN:
  Digital Audio OUT
- SILKSCREEN:
  Digital Audio IN
- DNP
sheet 10
- JTAG
- MISC connectors
- NXP refdes layout
- DNP
- TMS
- VCC
- TCK
- GND
- TDO
- GND
- TDI
- SILKSCREEN:
  JTAG
- DNP
- I2C to GPIO expander
- DNP
- DNP
- DNP
- DNP
- I2C Address:
  0x20
- DNP
- M.2 Level shifters
- I2C connection provision
- DNP
- DNP
- DNP
- OE VCCA
  domain
- DNP
- CAN Buses
- SILKSCREEN:
  | CAN1+ | CAN1- | GND | CAN2+ | CAN2- |
- DNP
- Align with P4 Pin layout physical dimention
- DNP
sheet 11
- MIPI-DSI LCD connector
- MIPI-DSI LCD back-light power
- # 100-Ohm diff pairs
- Typical LED configuration: Two parallel chains of 6 serially connected LEDs
- DNP
- # 100-Ohm diff pairs
- SILKSCREEN:
  MIPI-DSI LCD
- MIPI-DSI touch-panel connector
- SILKSCREEN:
  MIPI-DSI Touch Ctl.
- Pinout of J5 reversed
   to FPC
- GT911 supports two I2C slave
  addresses: 0xBA/0xBB and 0x28/0x29.
  The host can select the address by
  changing the status of Reset and INT
  pins during the power-on
  initialization phase, refer:
  139D10080 Data Sheet, page 29
